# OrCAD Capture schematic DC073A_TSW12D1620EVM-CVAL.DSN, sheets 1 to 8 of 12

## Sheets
1 PAGE08 - MSP430: size B; title: SCH, TSW12D1620EVM-CVAL; rev: A; note: DC073
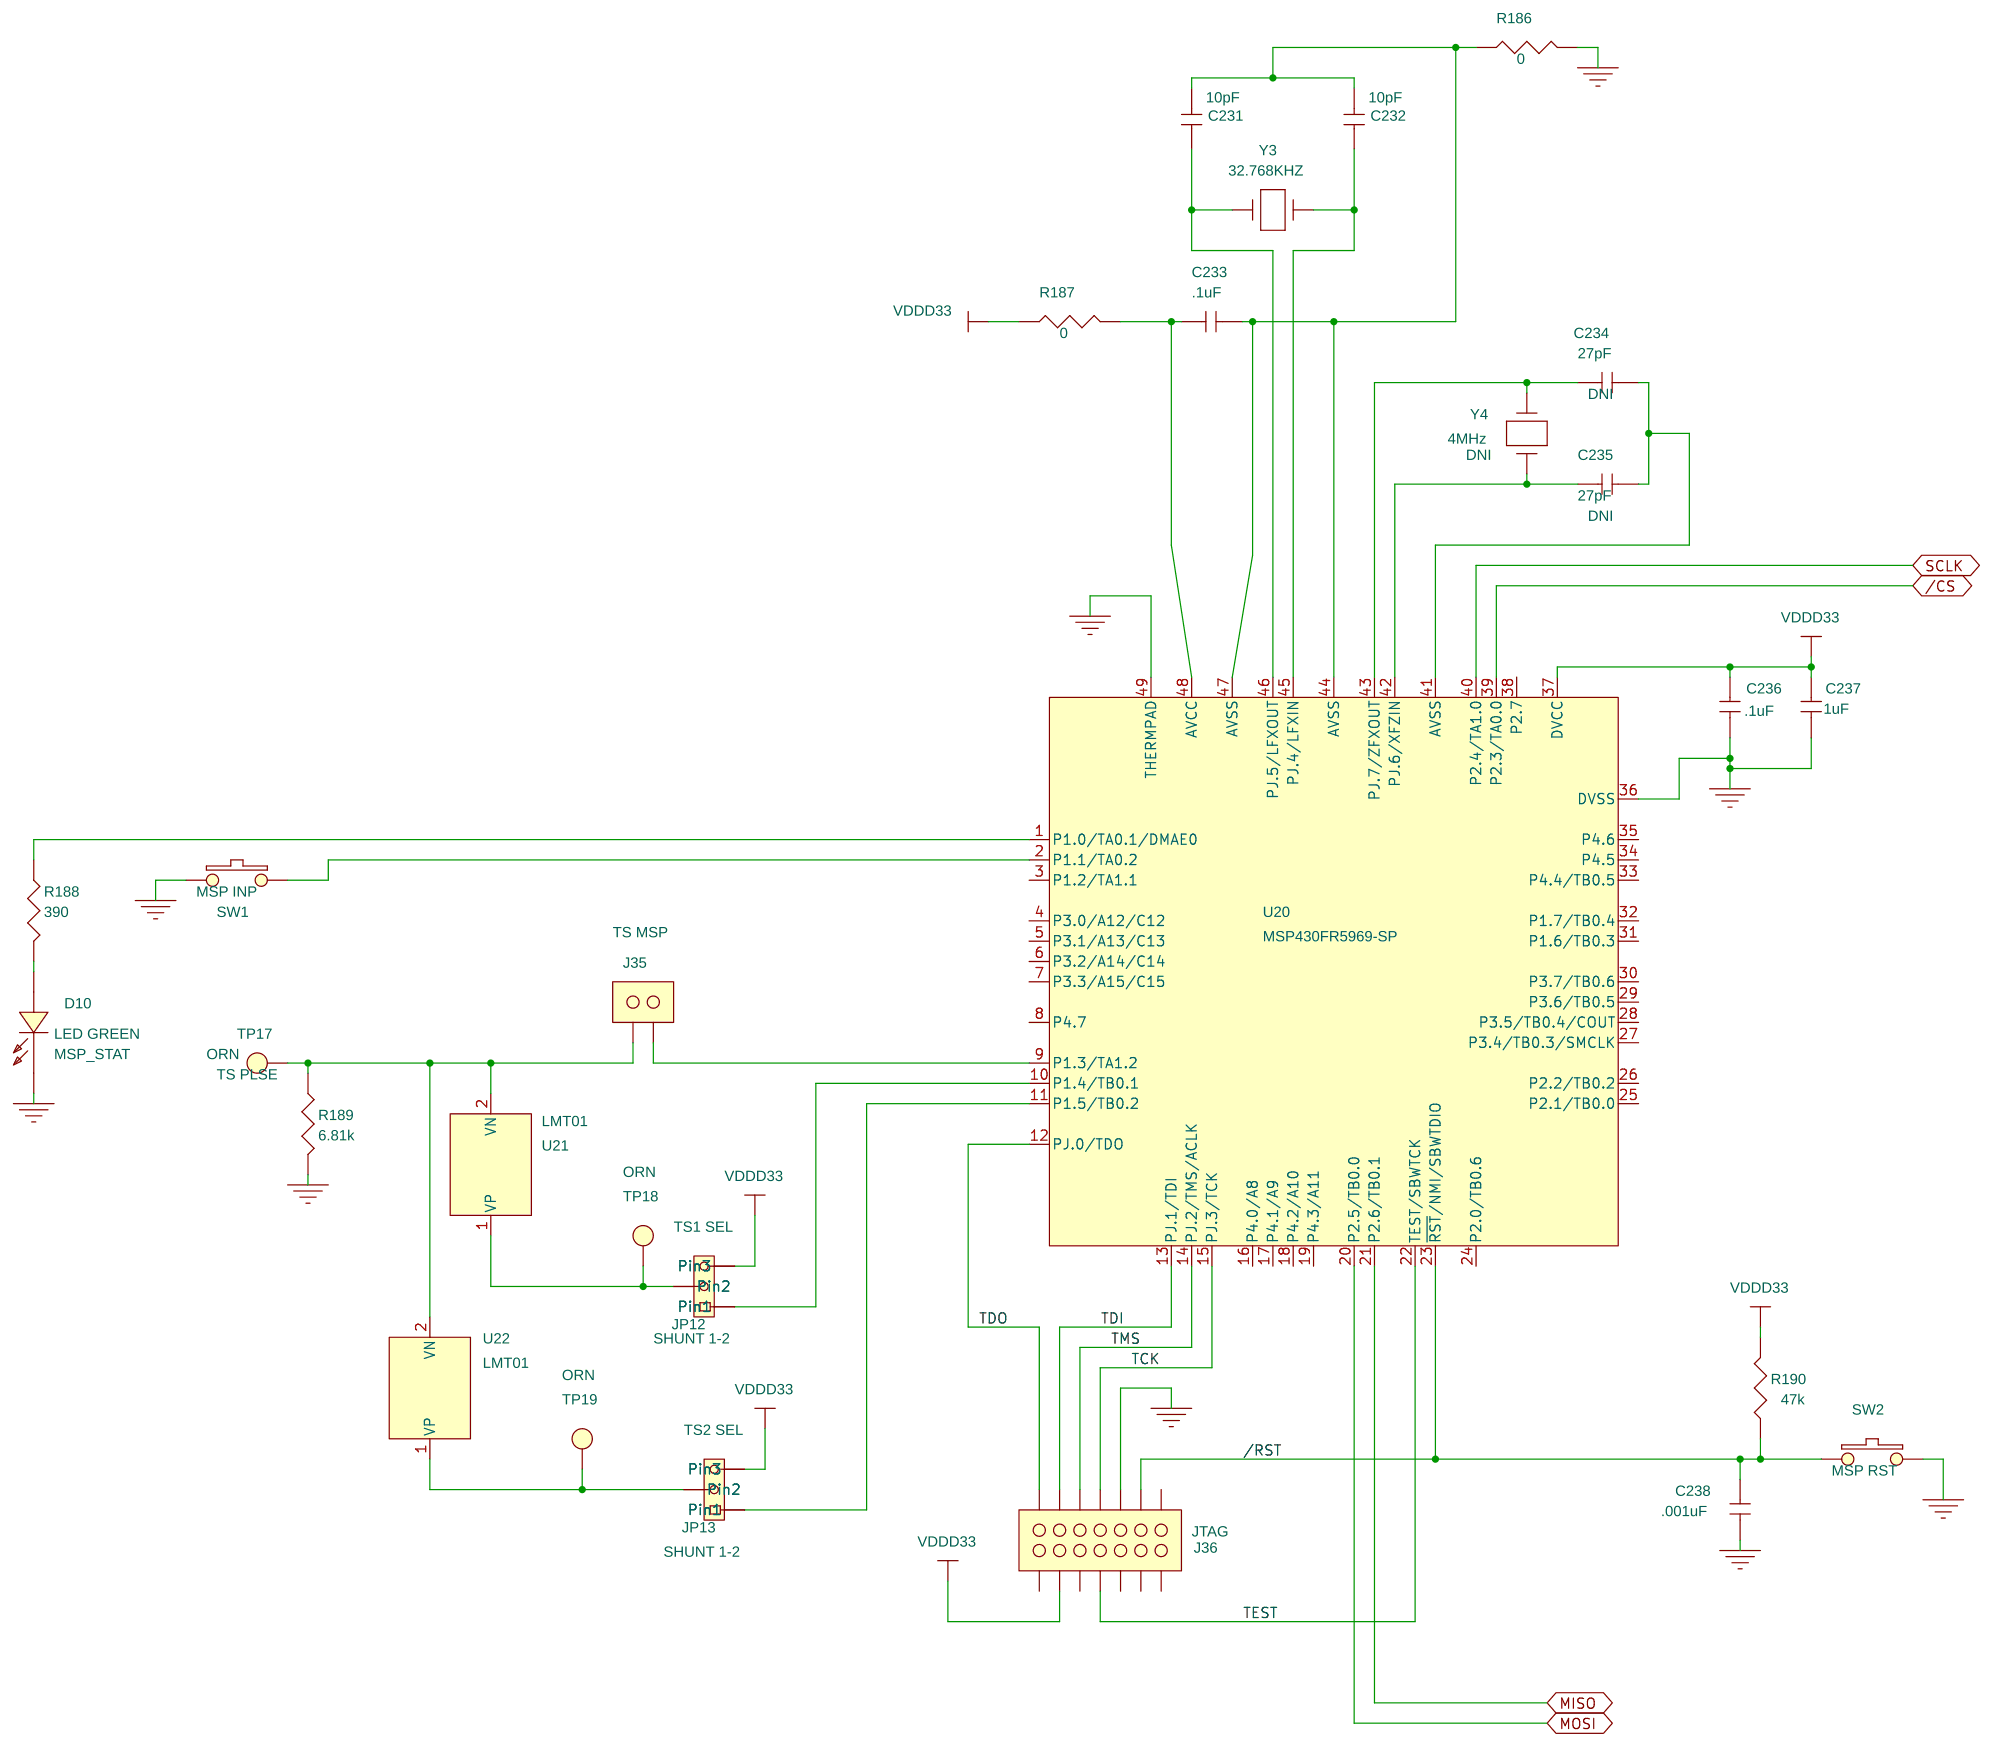
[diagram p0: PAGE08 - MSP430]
2 PAGE01 - BLOCK DIAGRAM
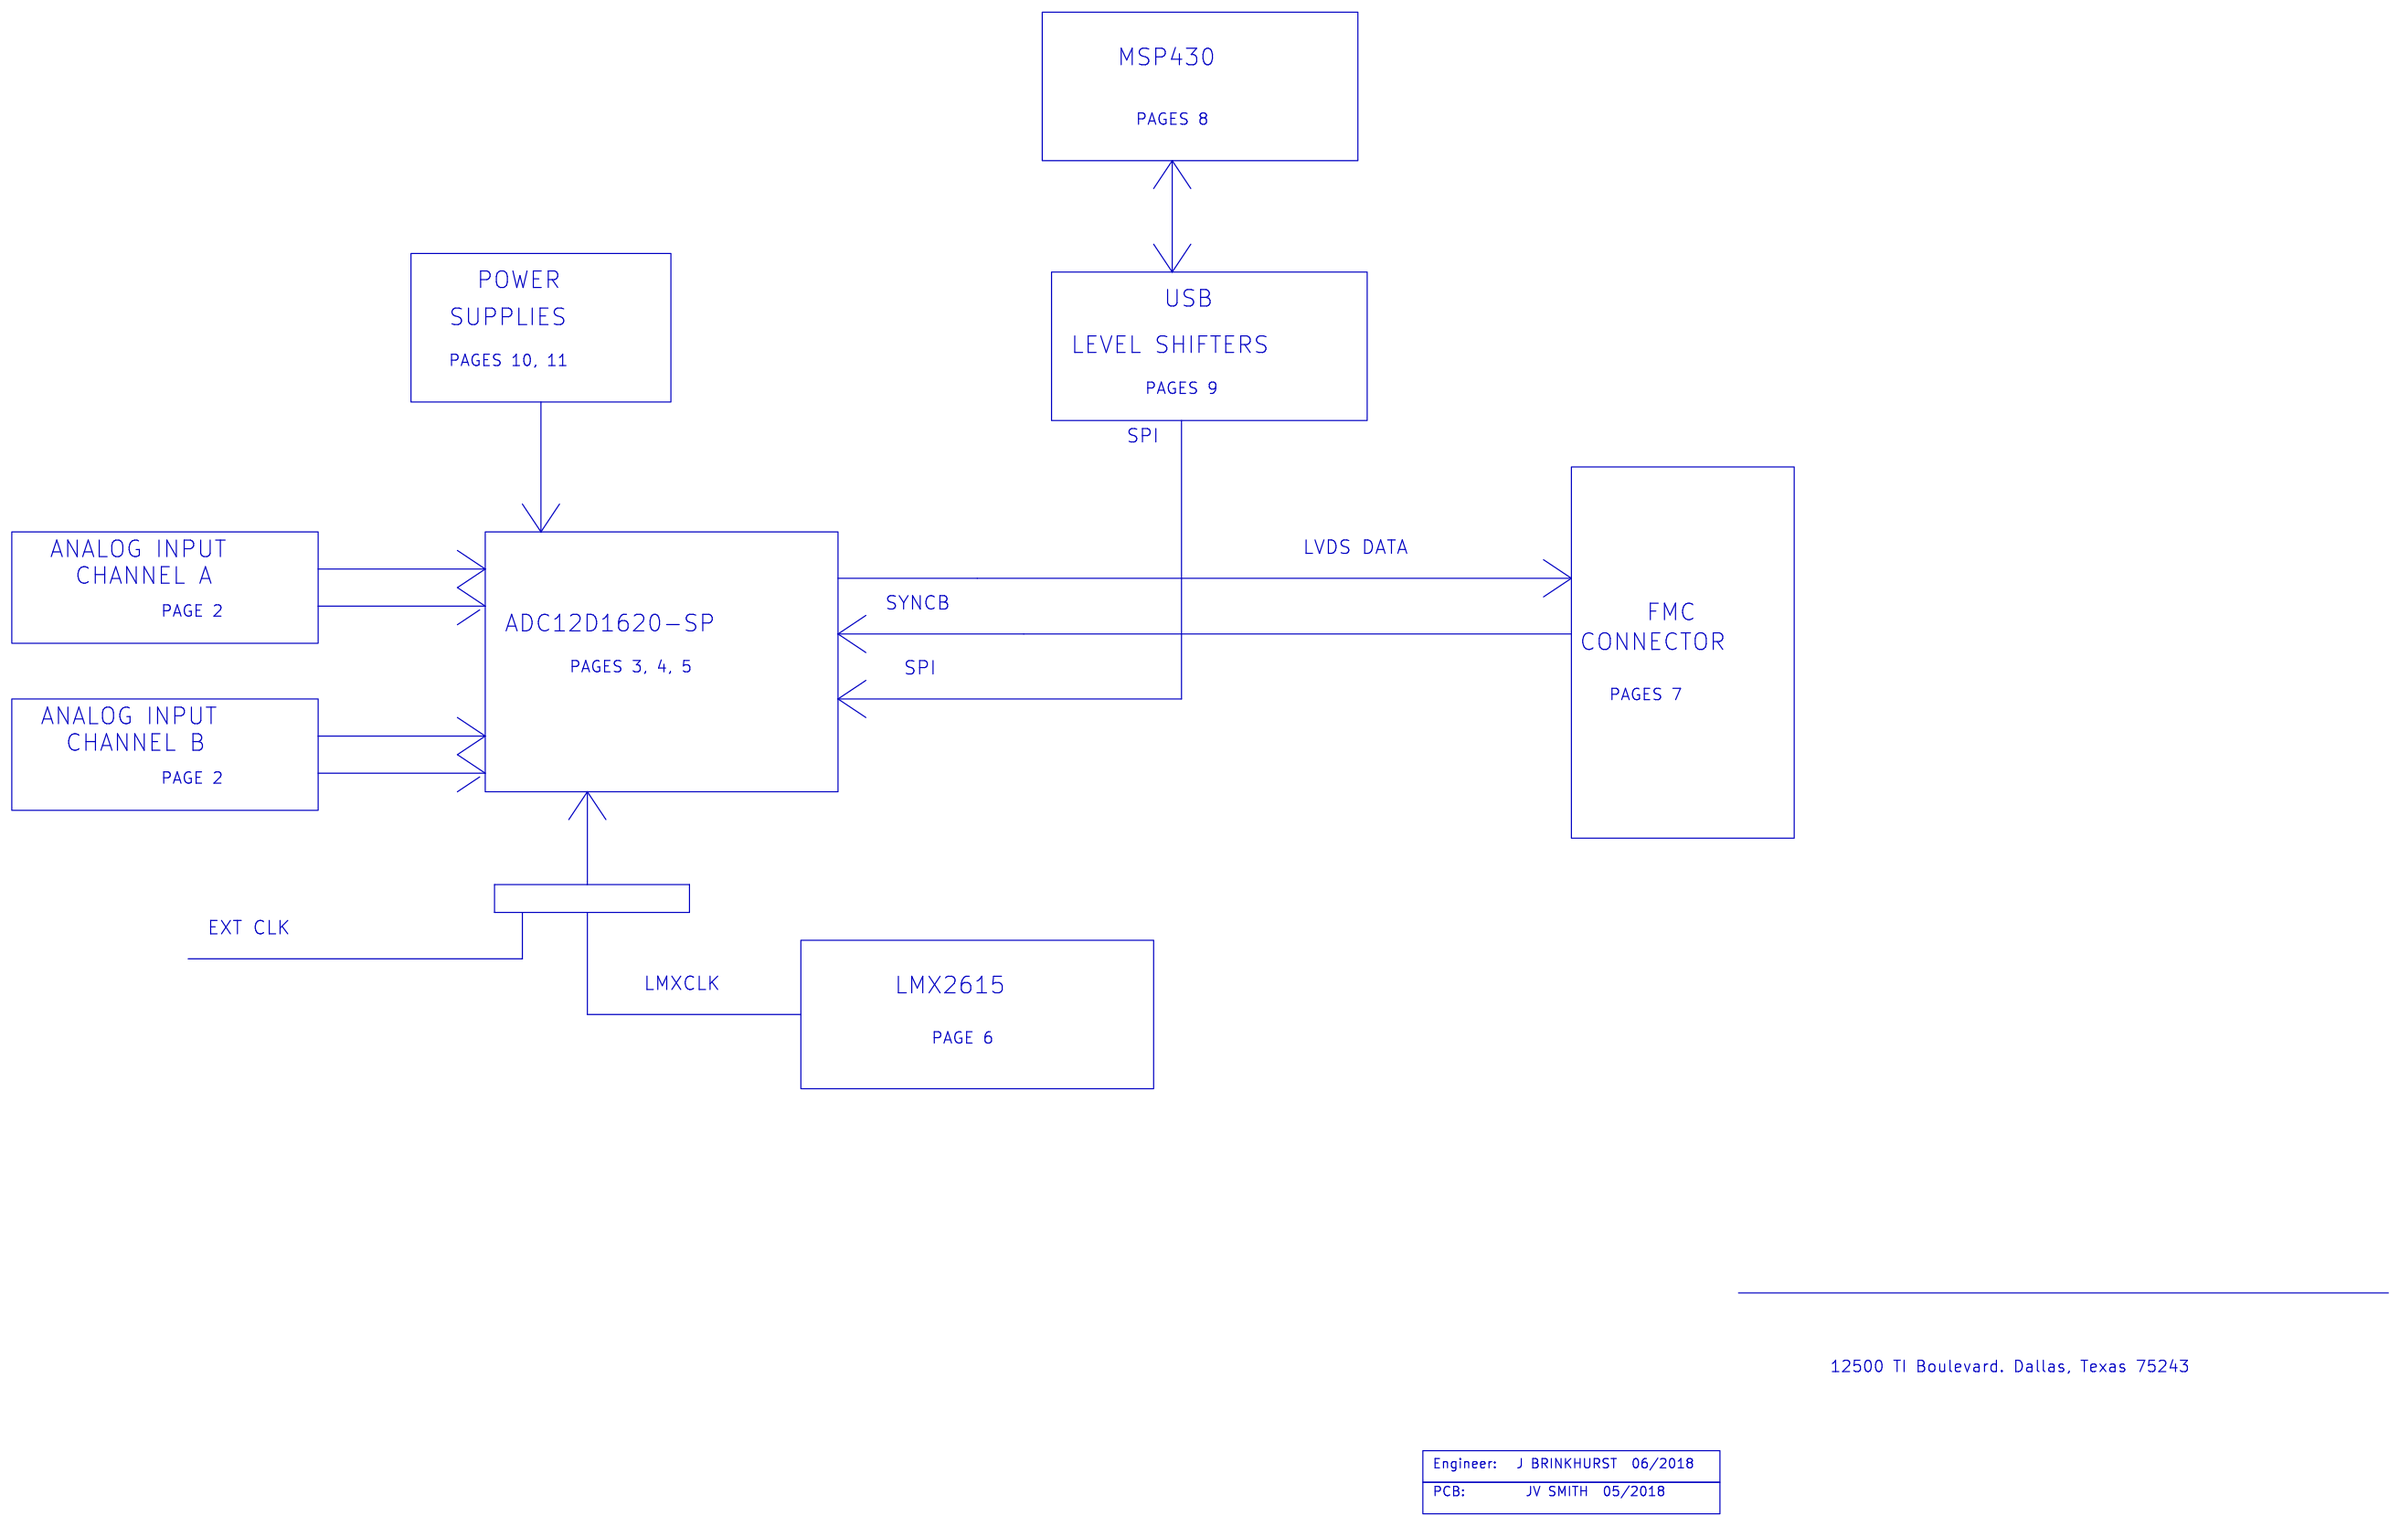
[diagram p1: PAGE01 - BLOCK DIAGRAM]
3 PAGE02 - ADC ANALOG INPUT: size B
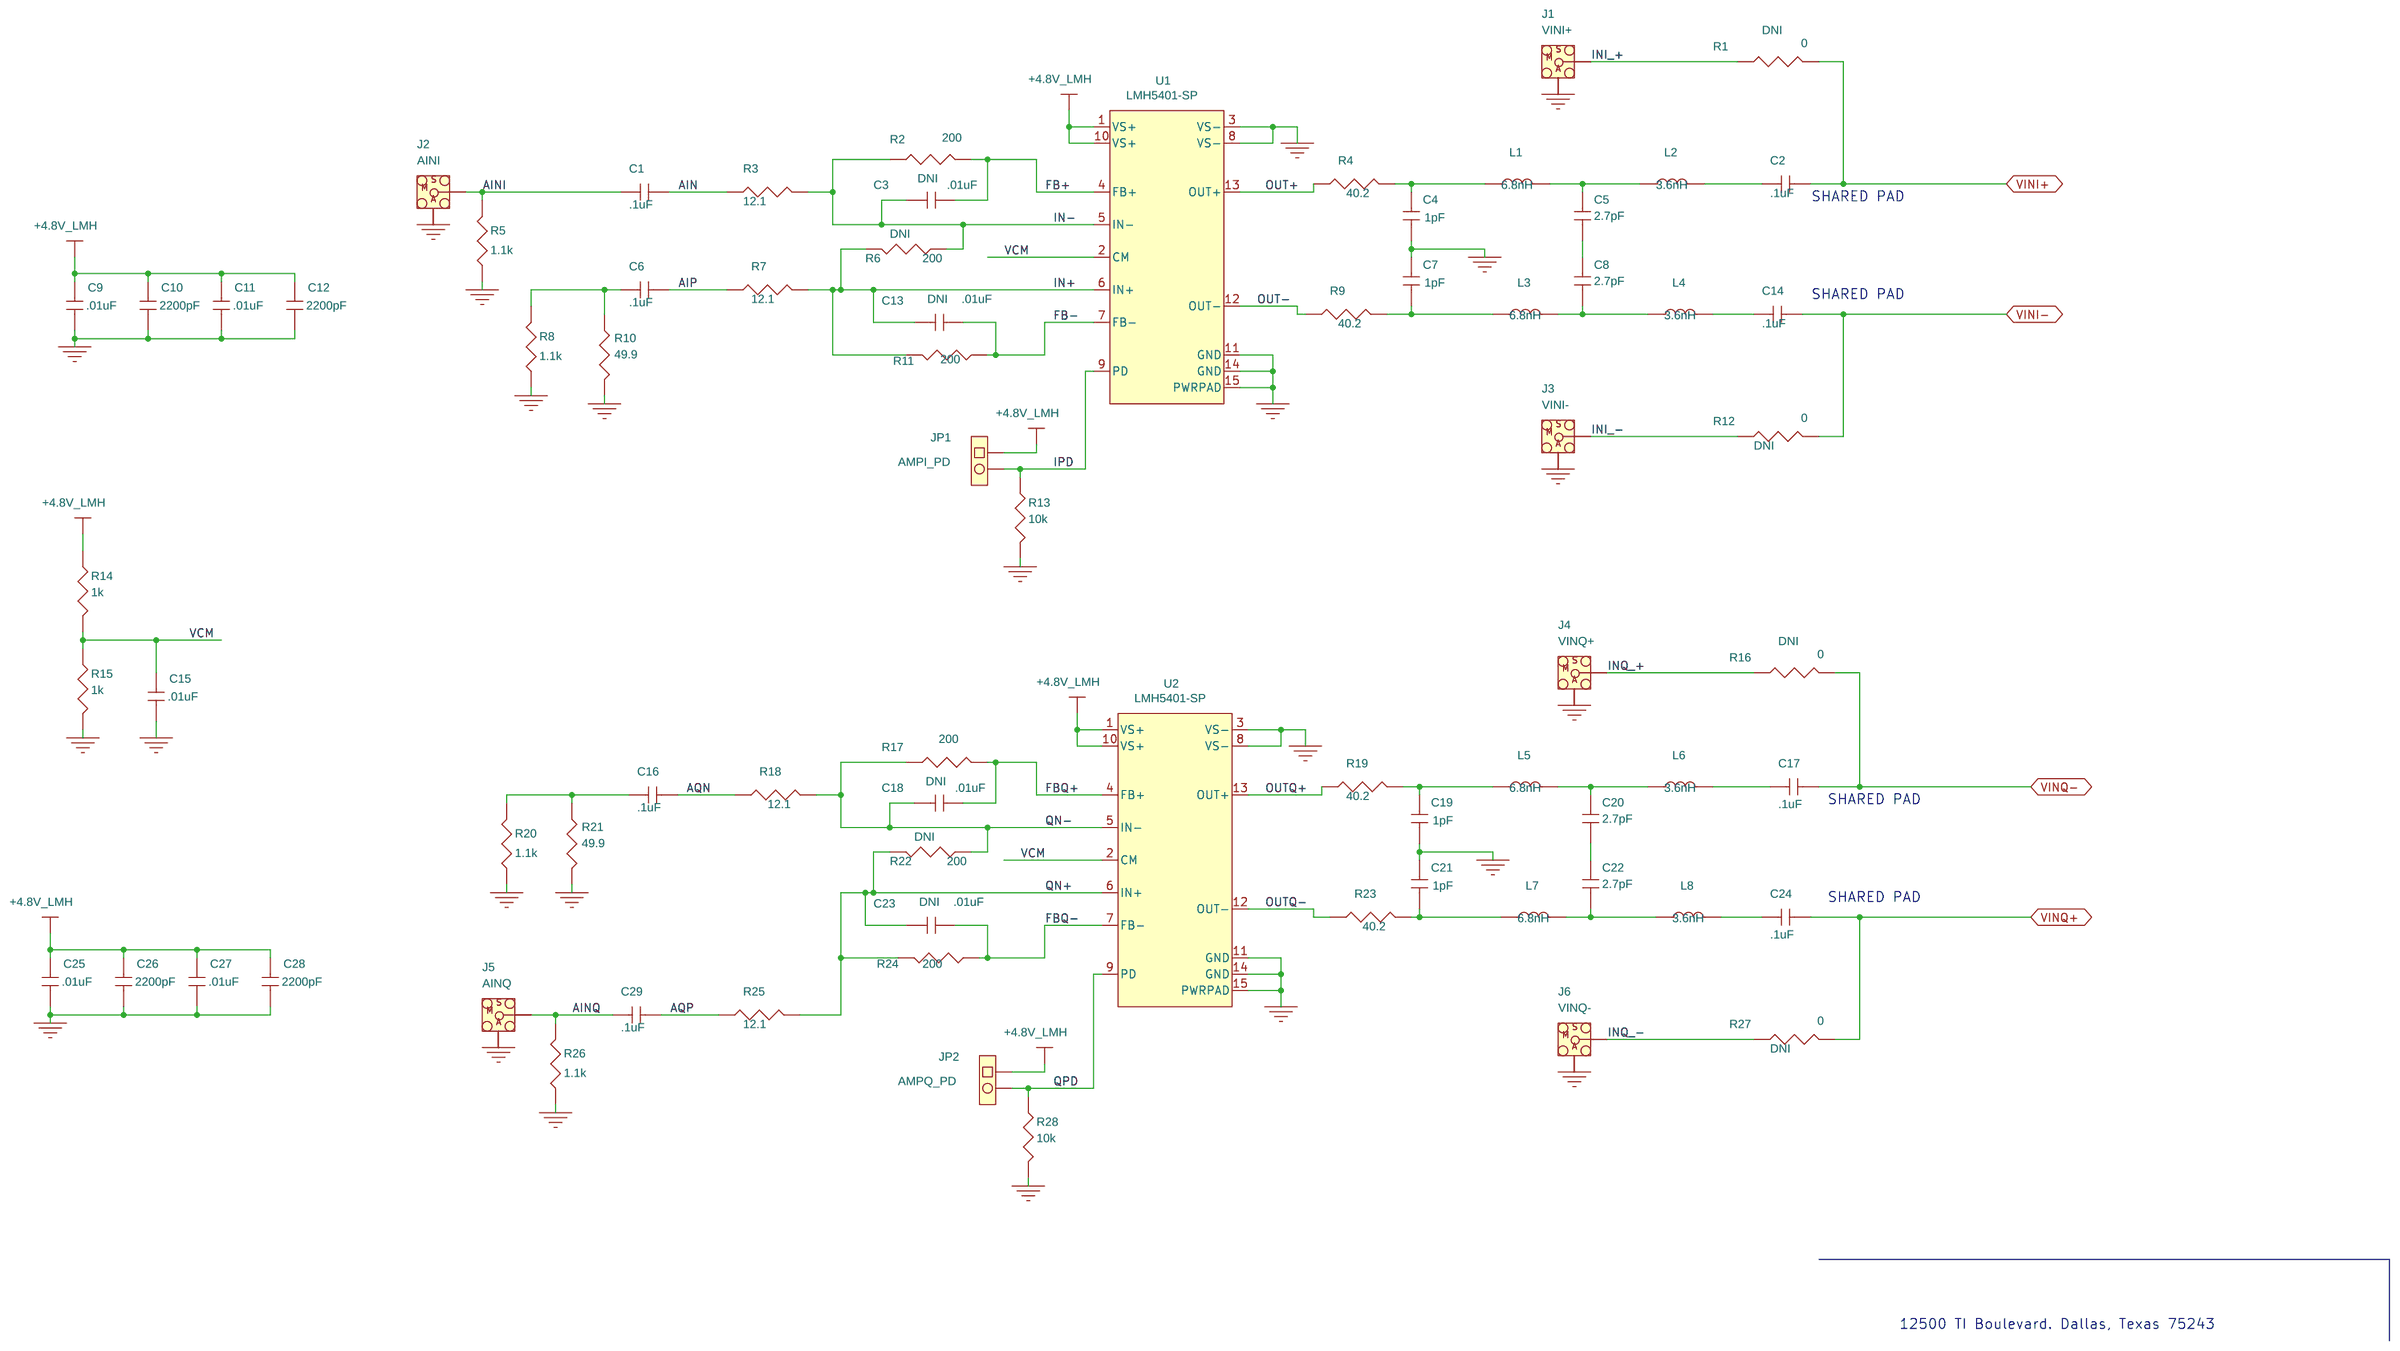
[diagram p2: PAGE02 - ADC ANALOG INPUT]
4 PAGE03 - ADC SPI: size B
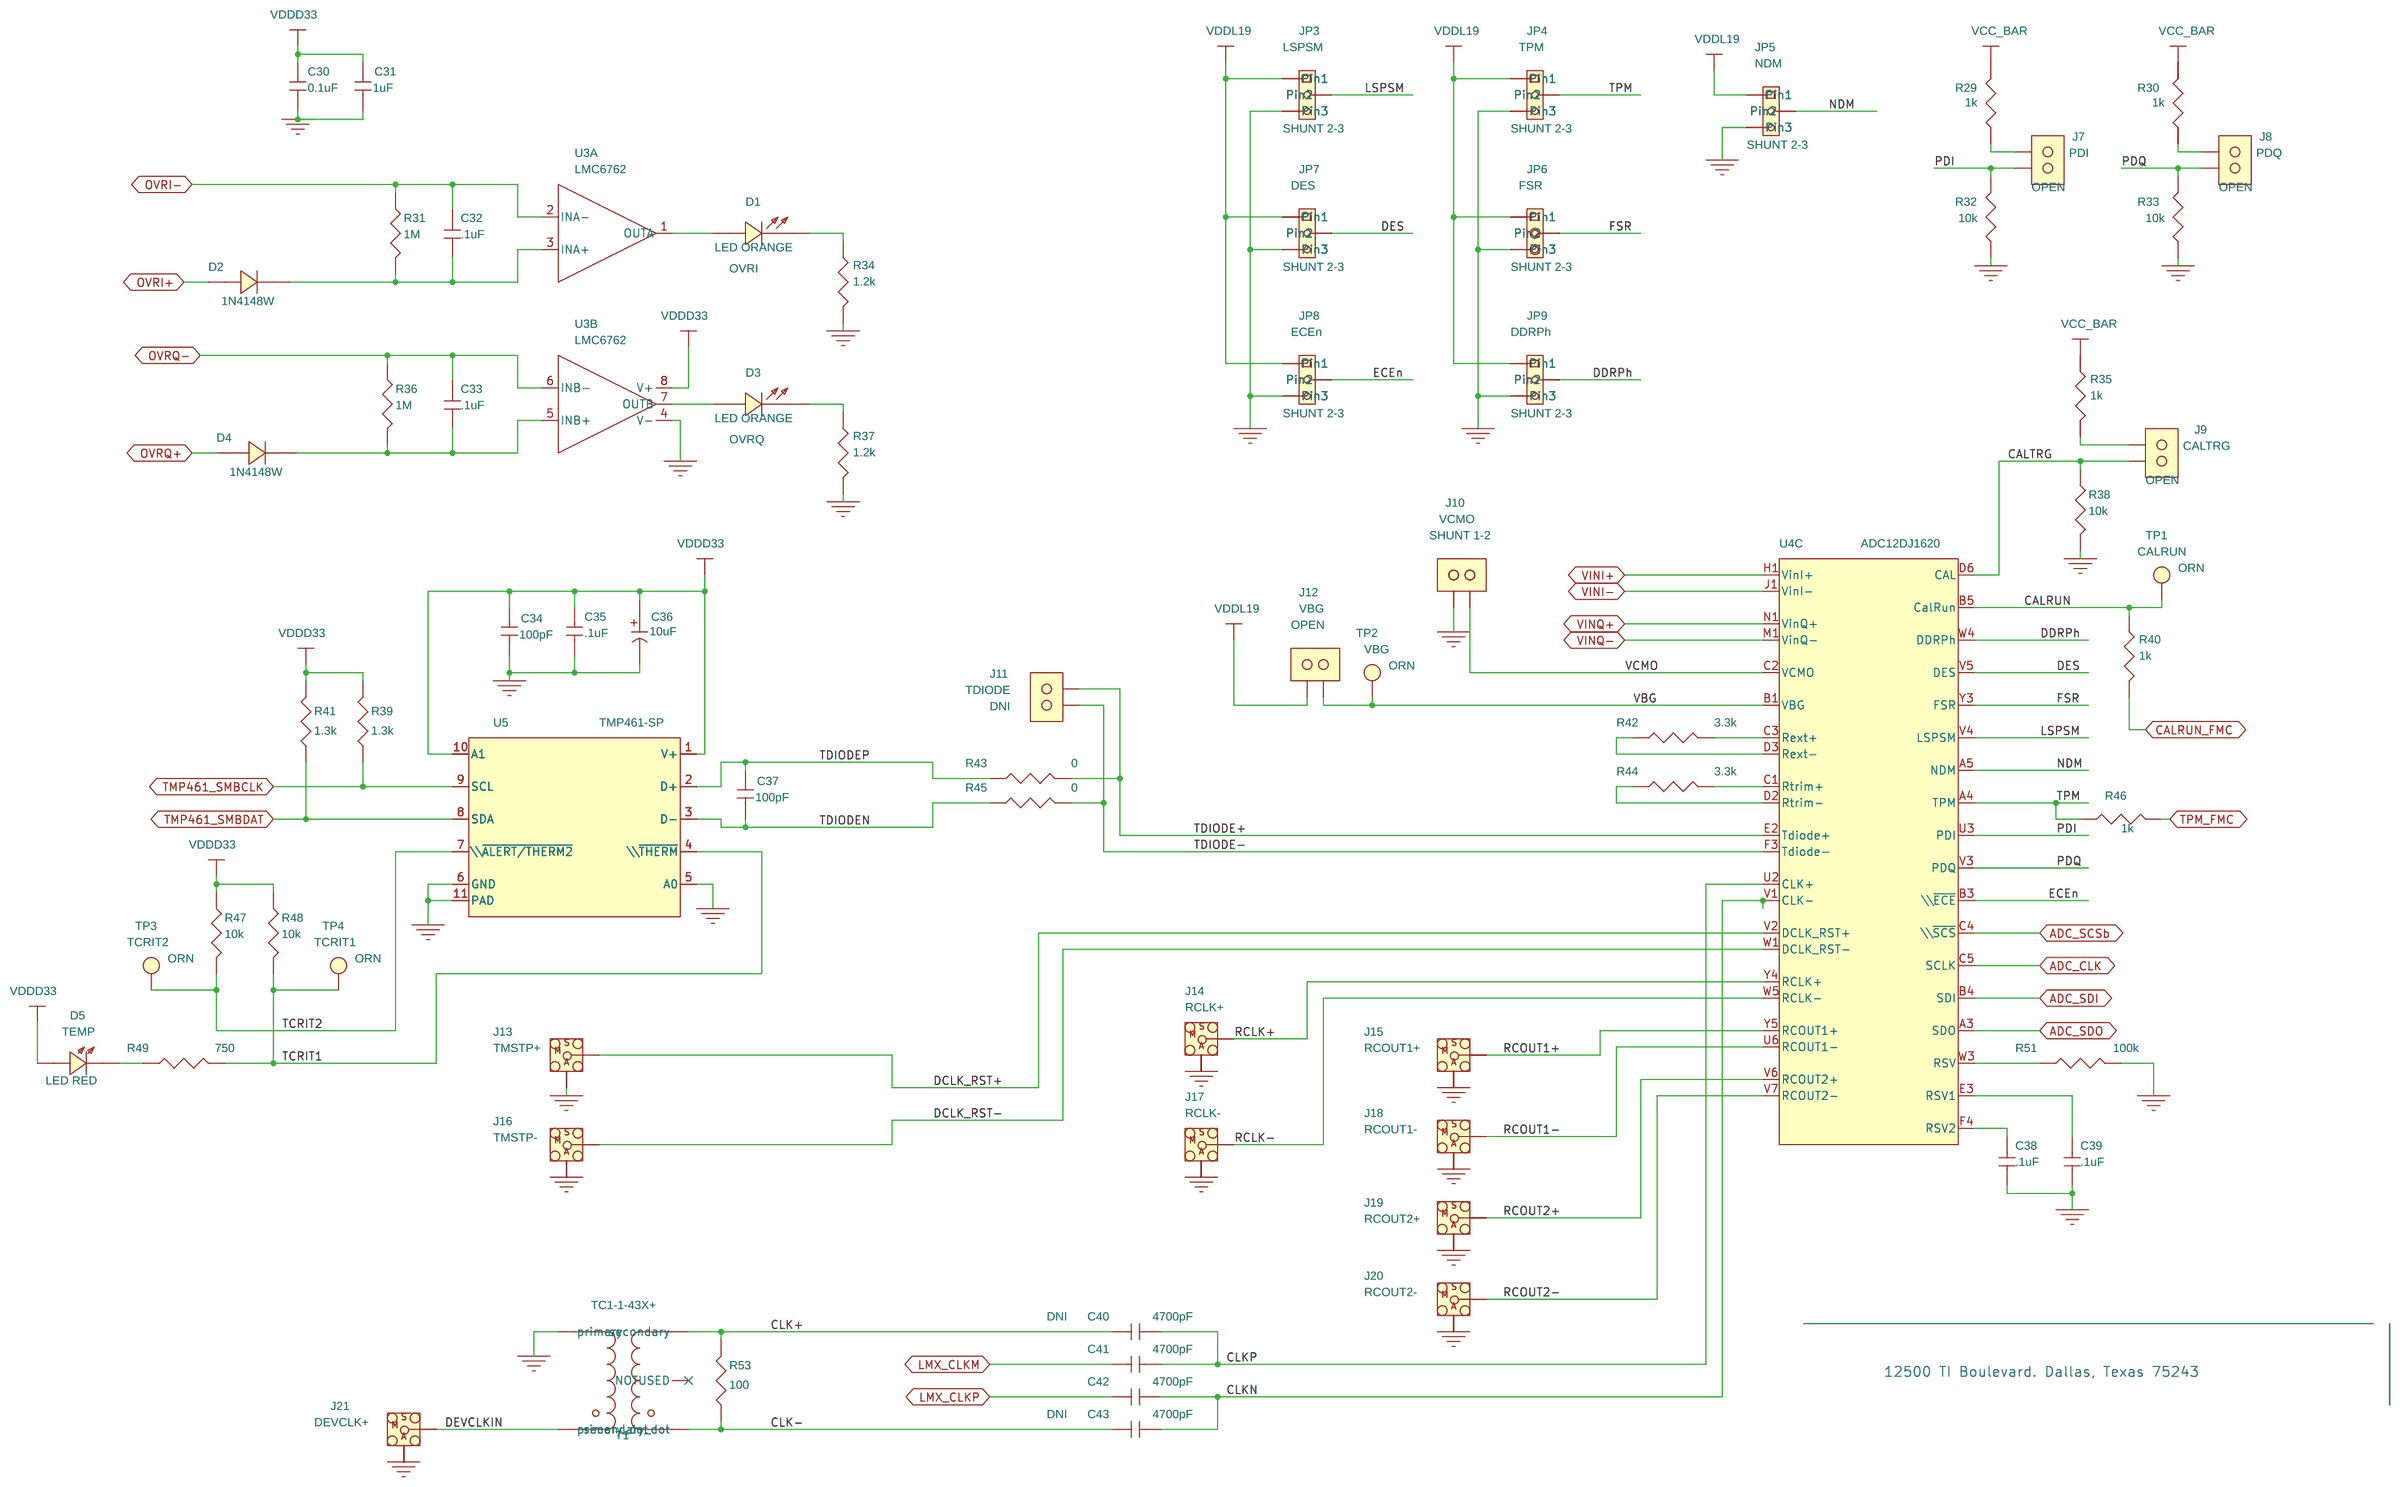
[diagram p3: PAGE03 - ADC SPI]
5 PAGE04 - ADC FMC CONNECTIONS: size B
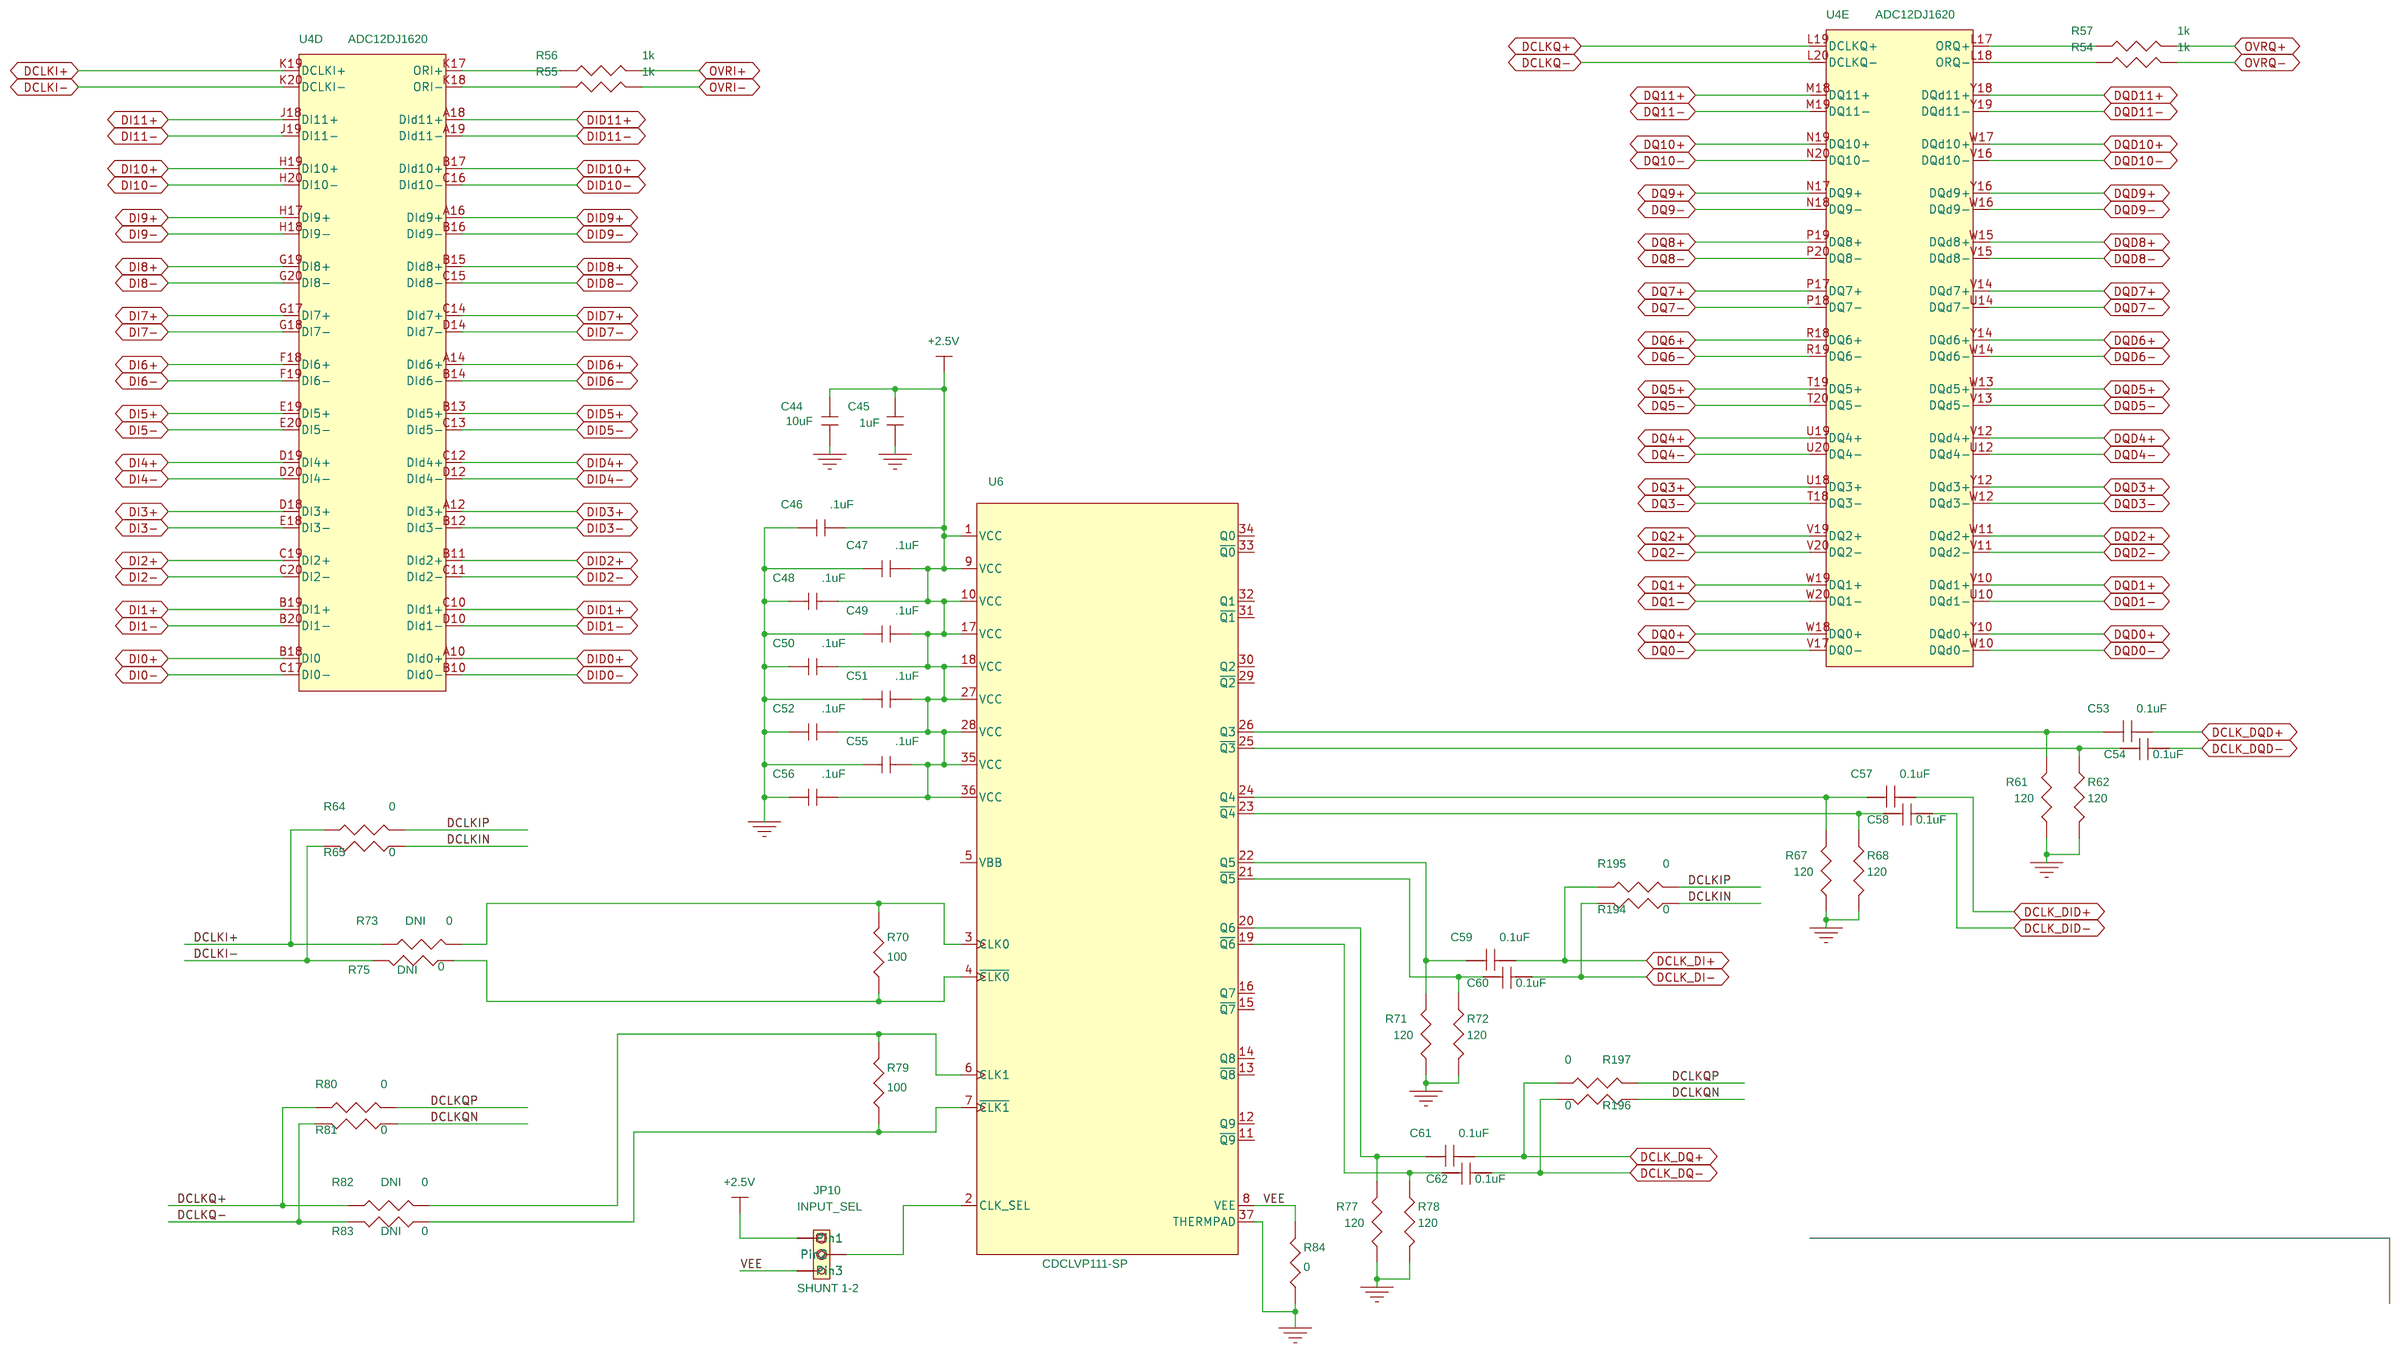
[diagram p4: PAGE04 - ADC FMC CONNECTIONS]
6 PAGE05 - ADC PWR: size B
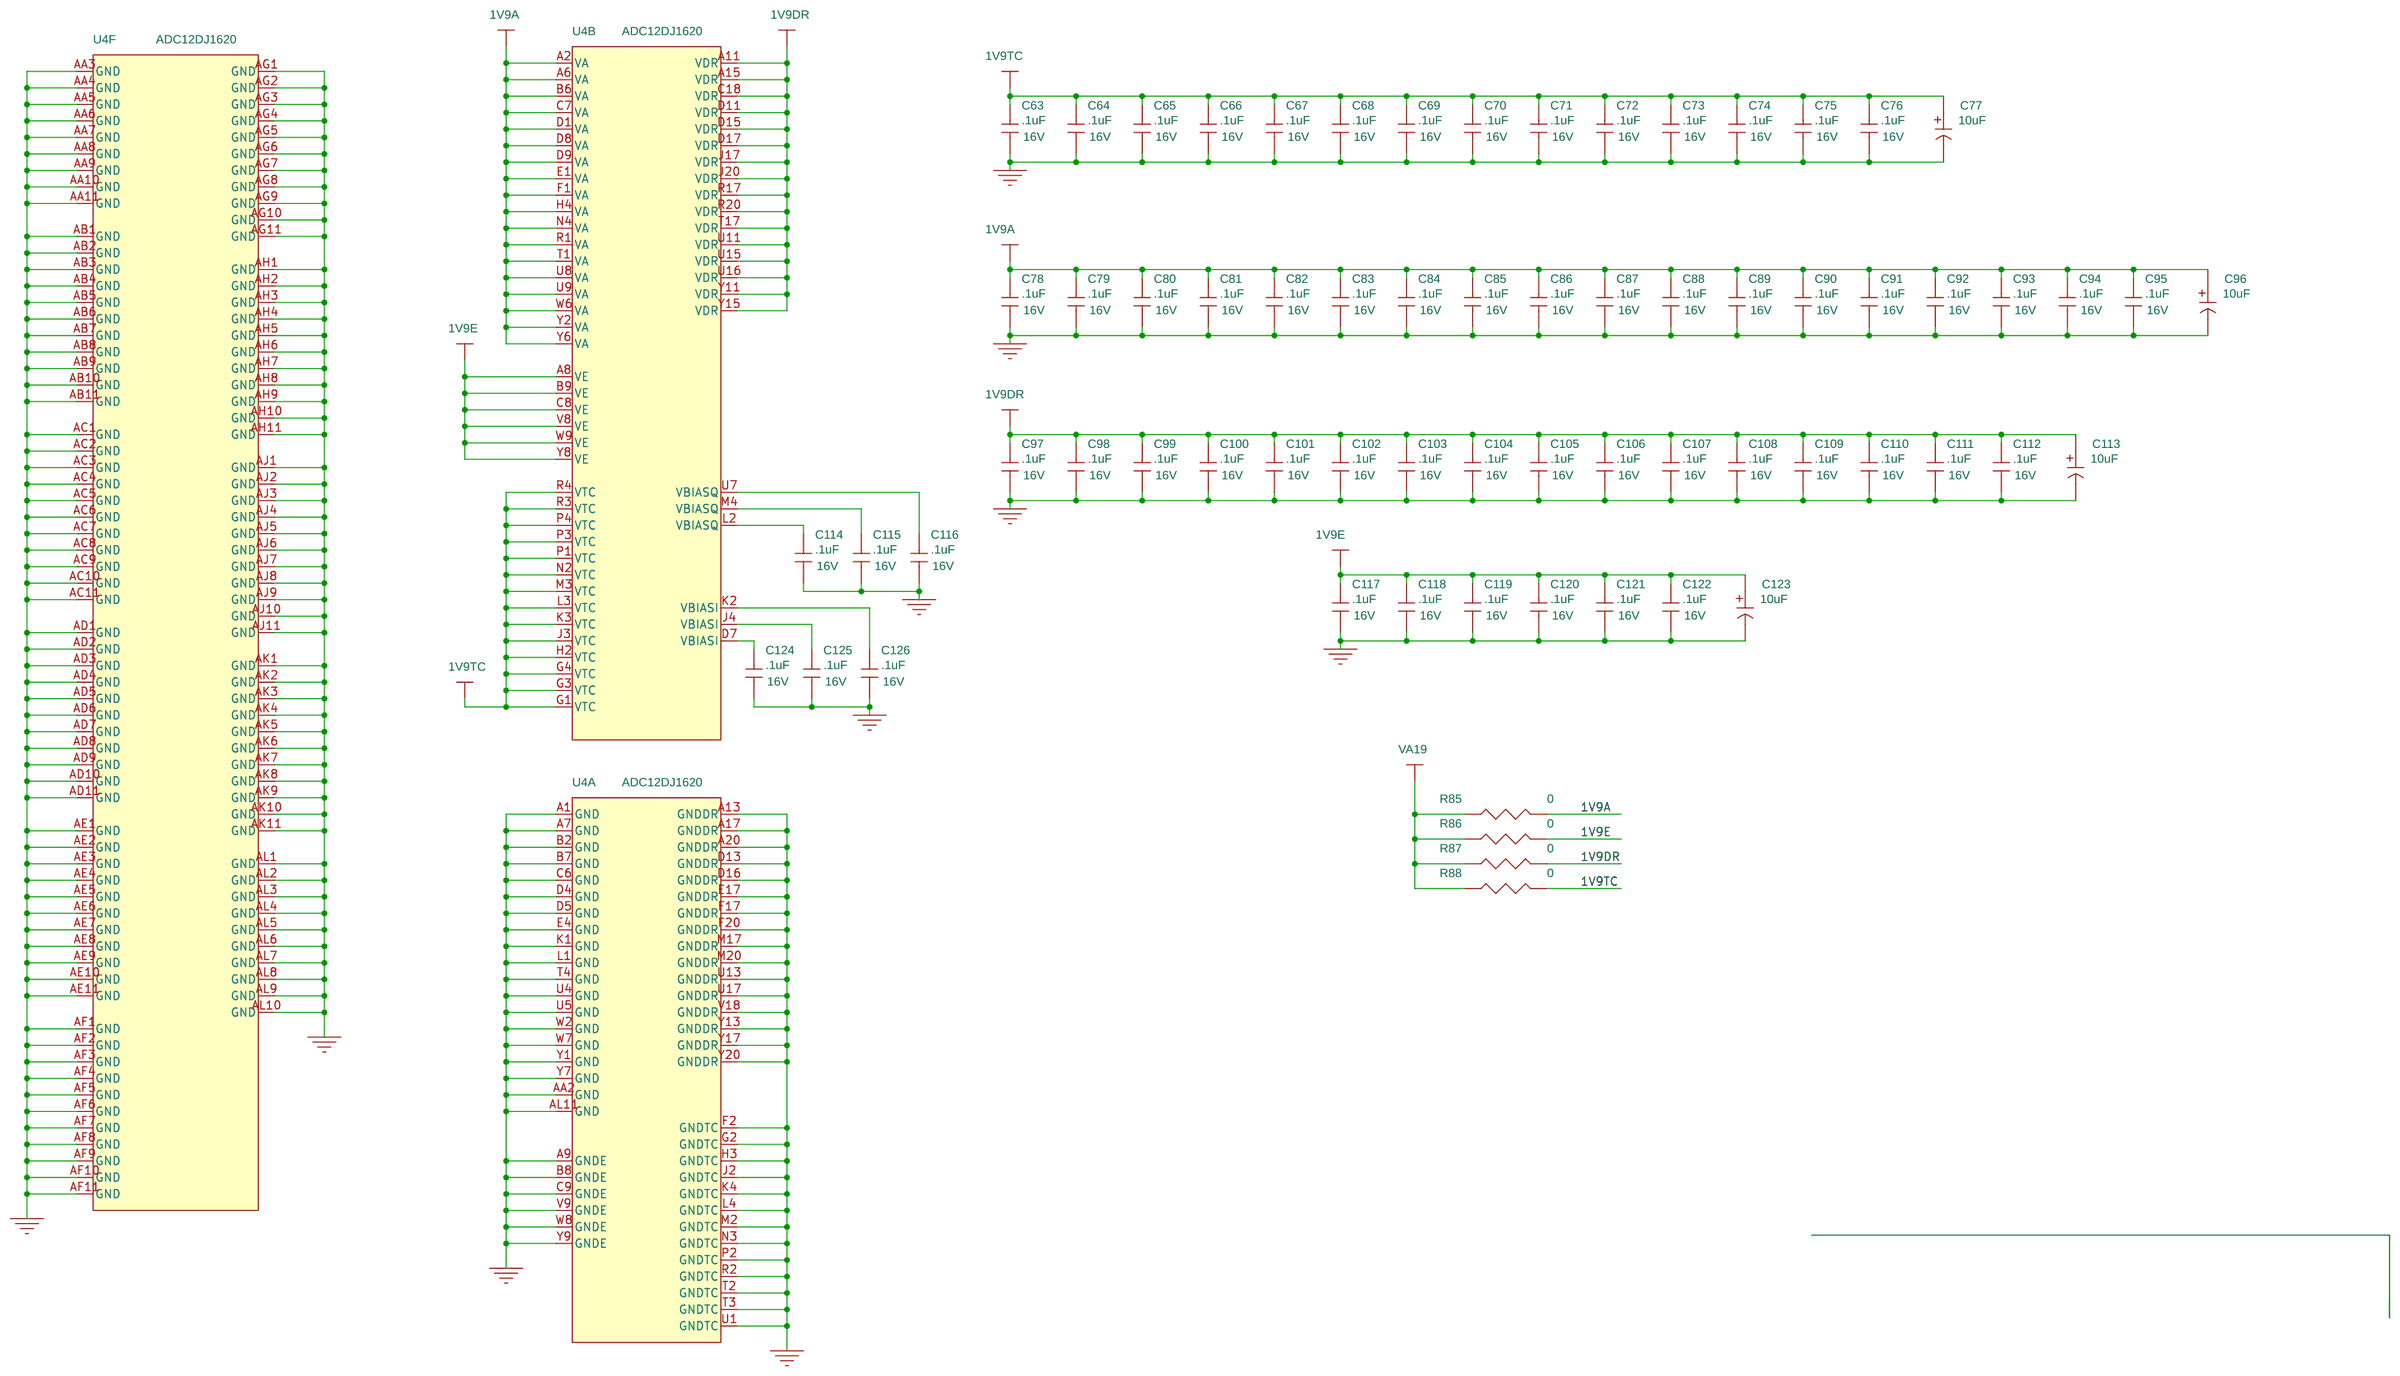
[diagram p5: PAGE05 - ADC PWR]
7 PAGE06 - LMX: size B
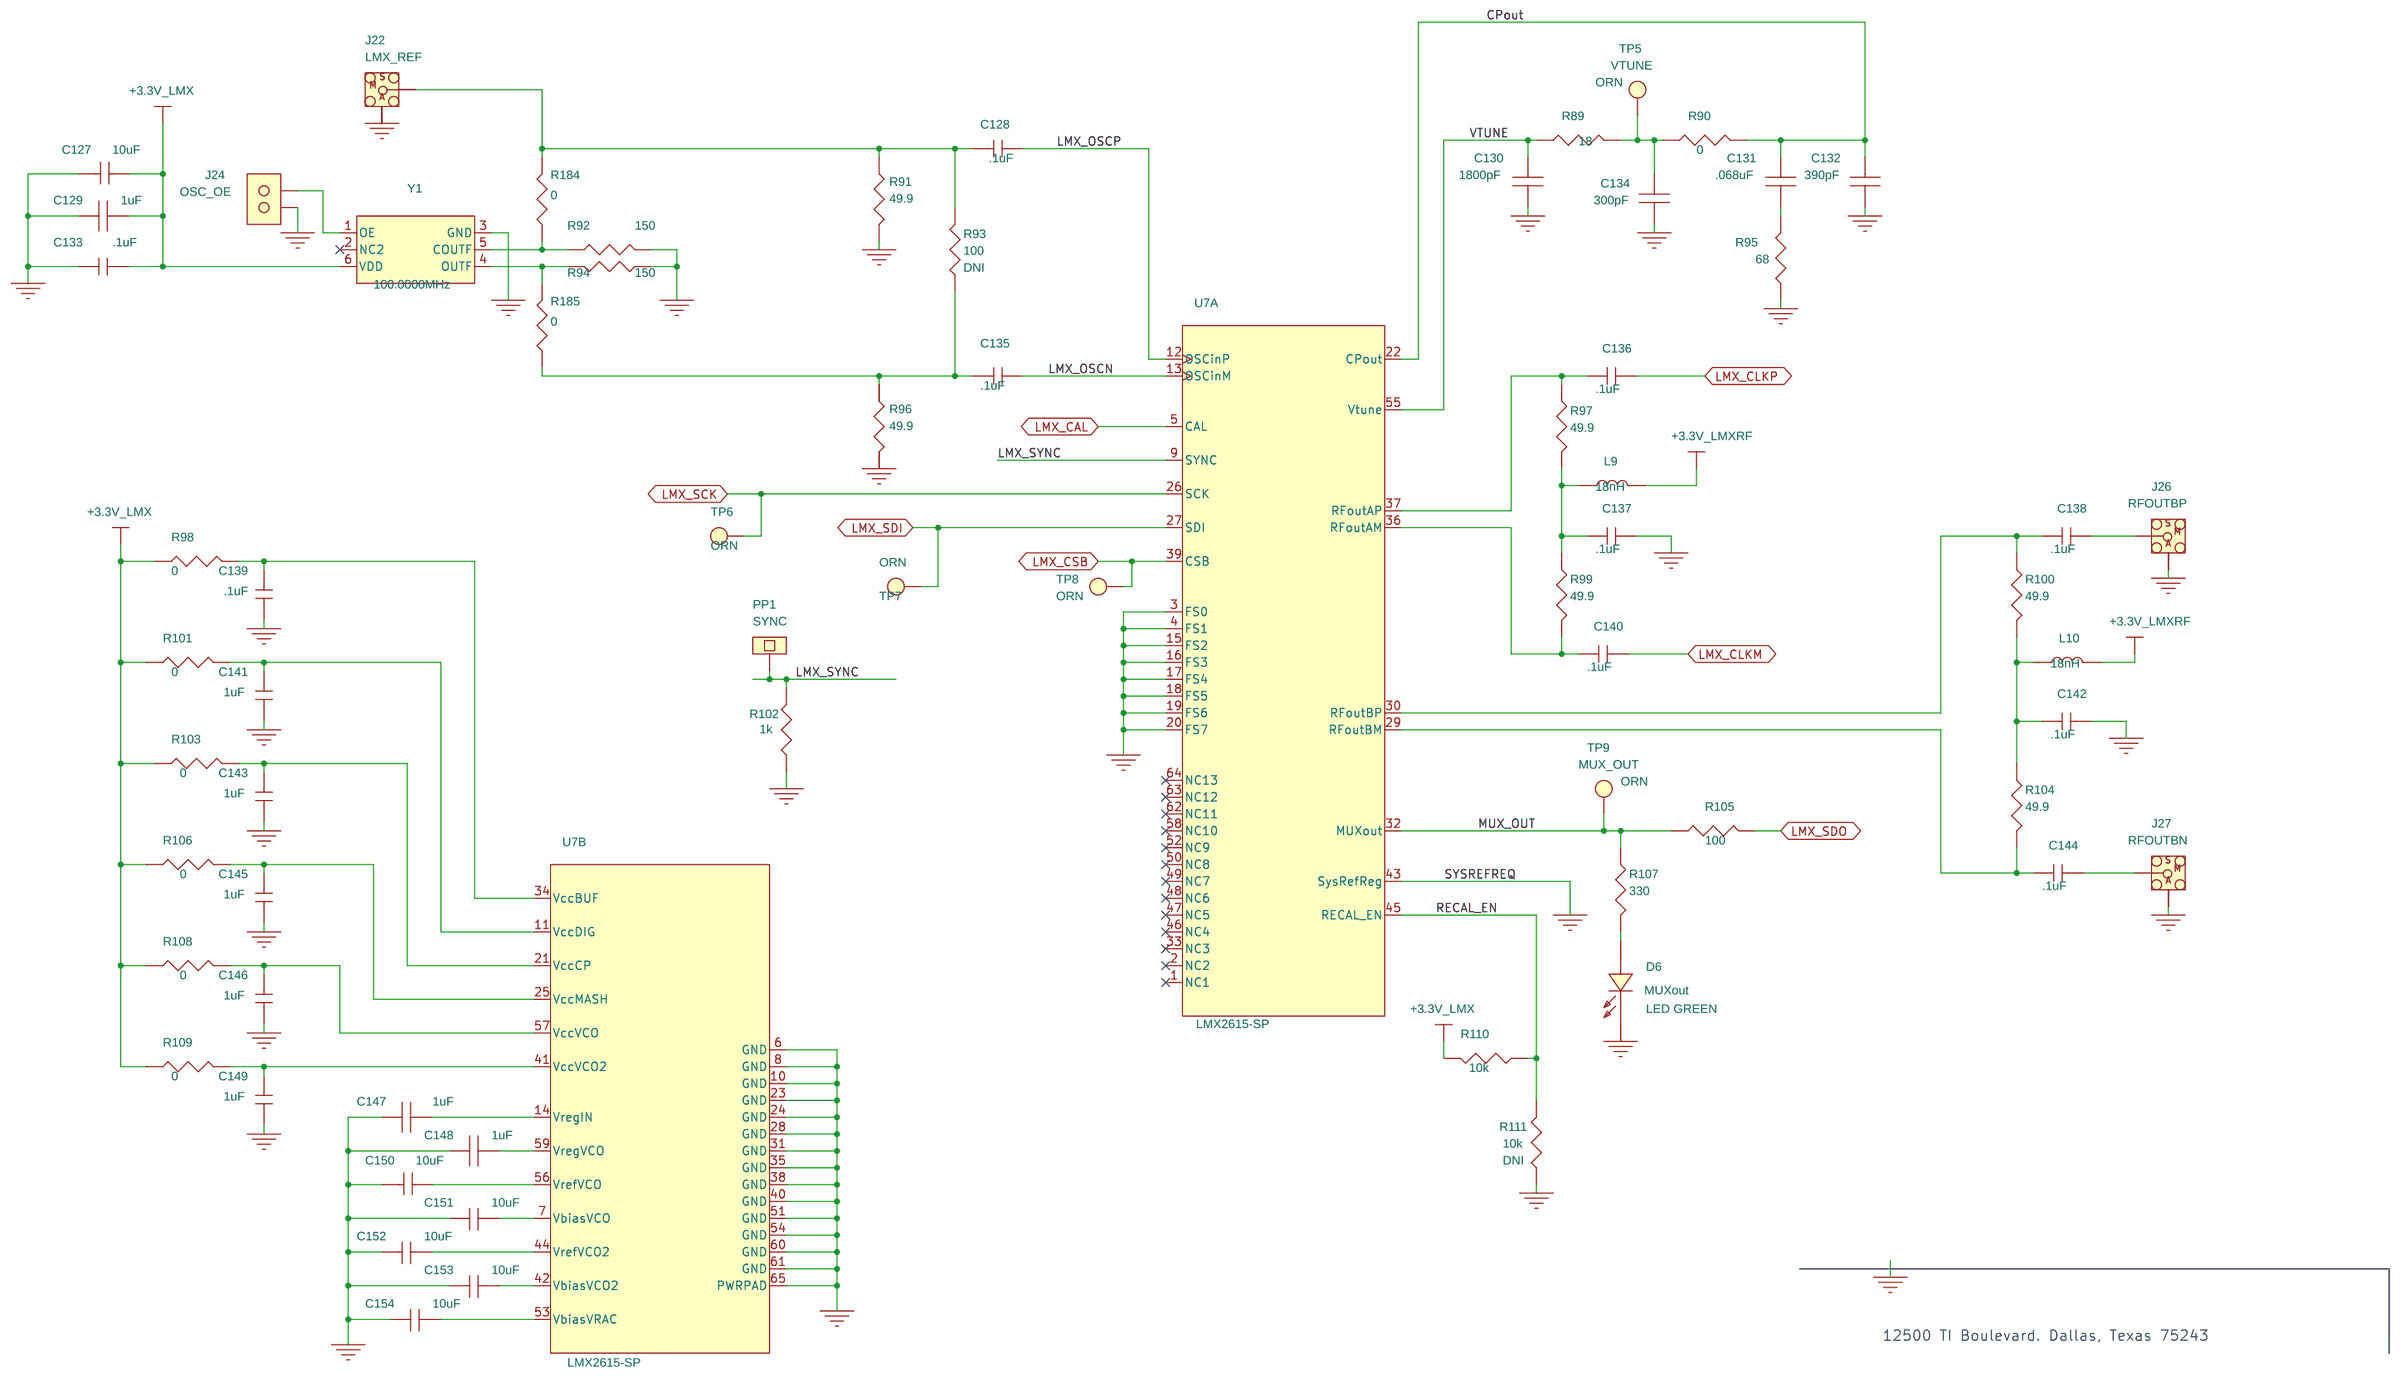
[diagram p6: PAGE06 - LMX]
8 PAGE07 - OUTPUT FMC CONN: size B
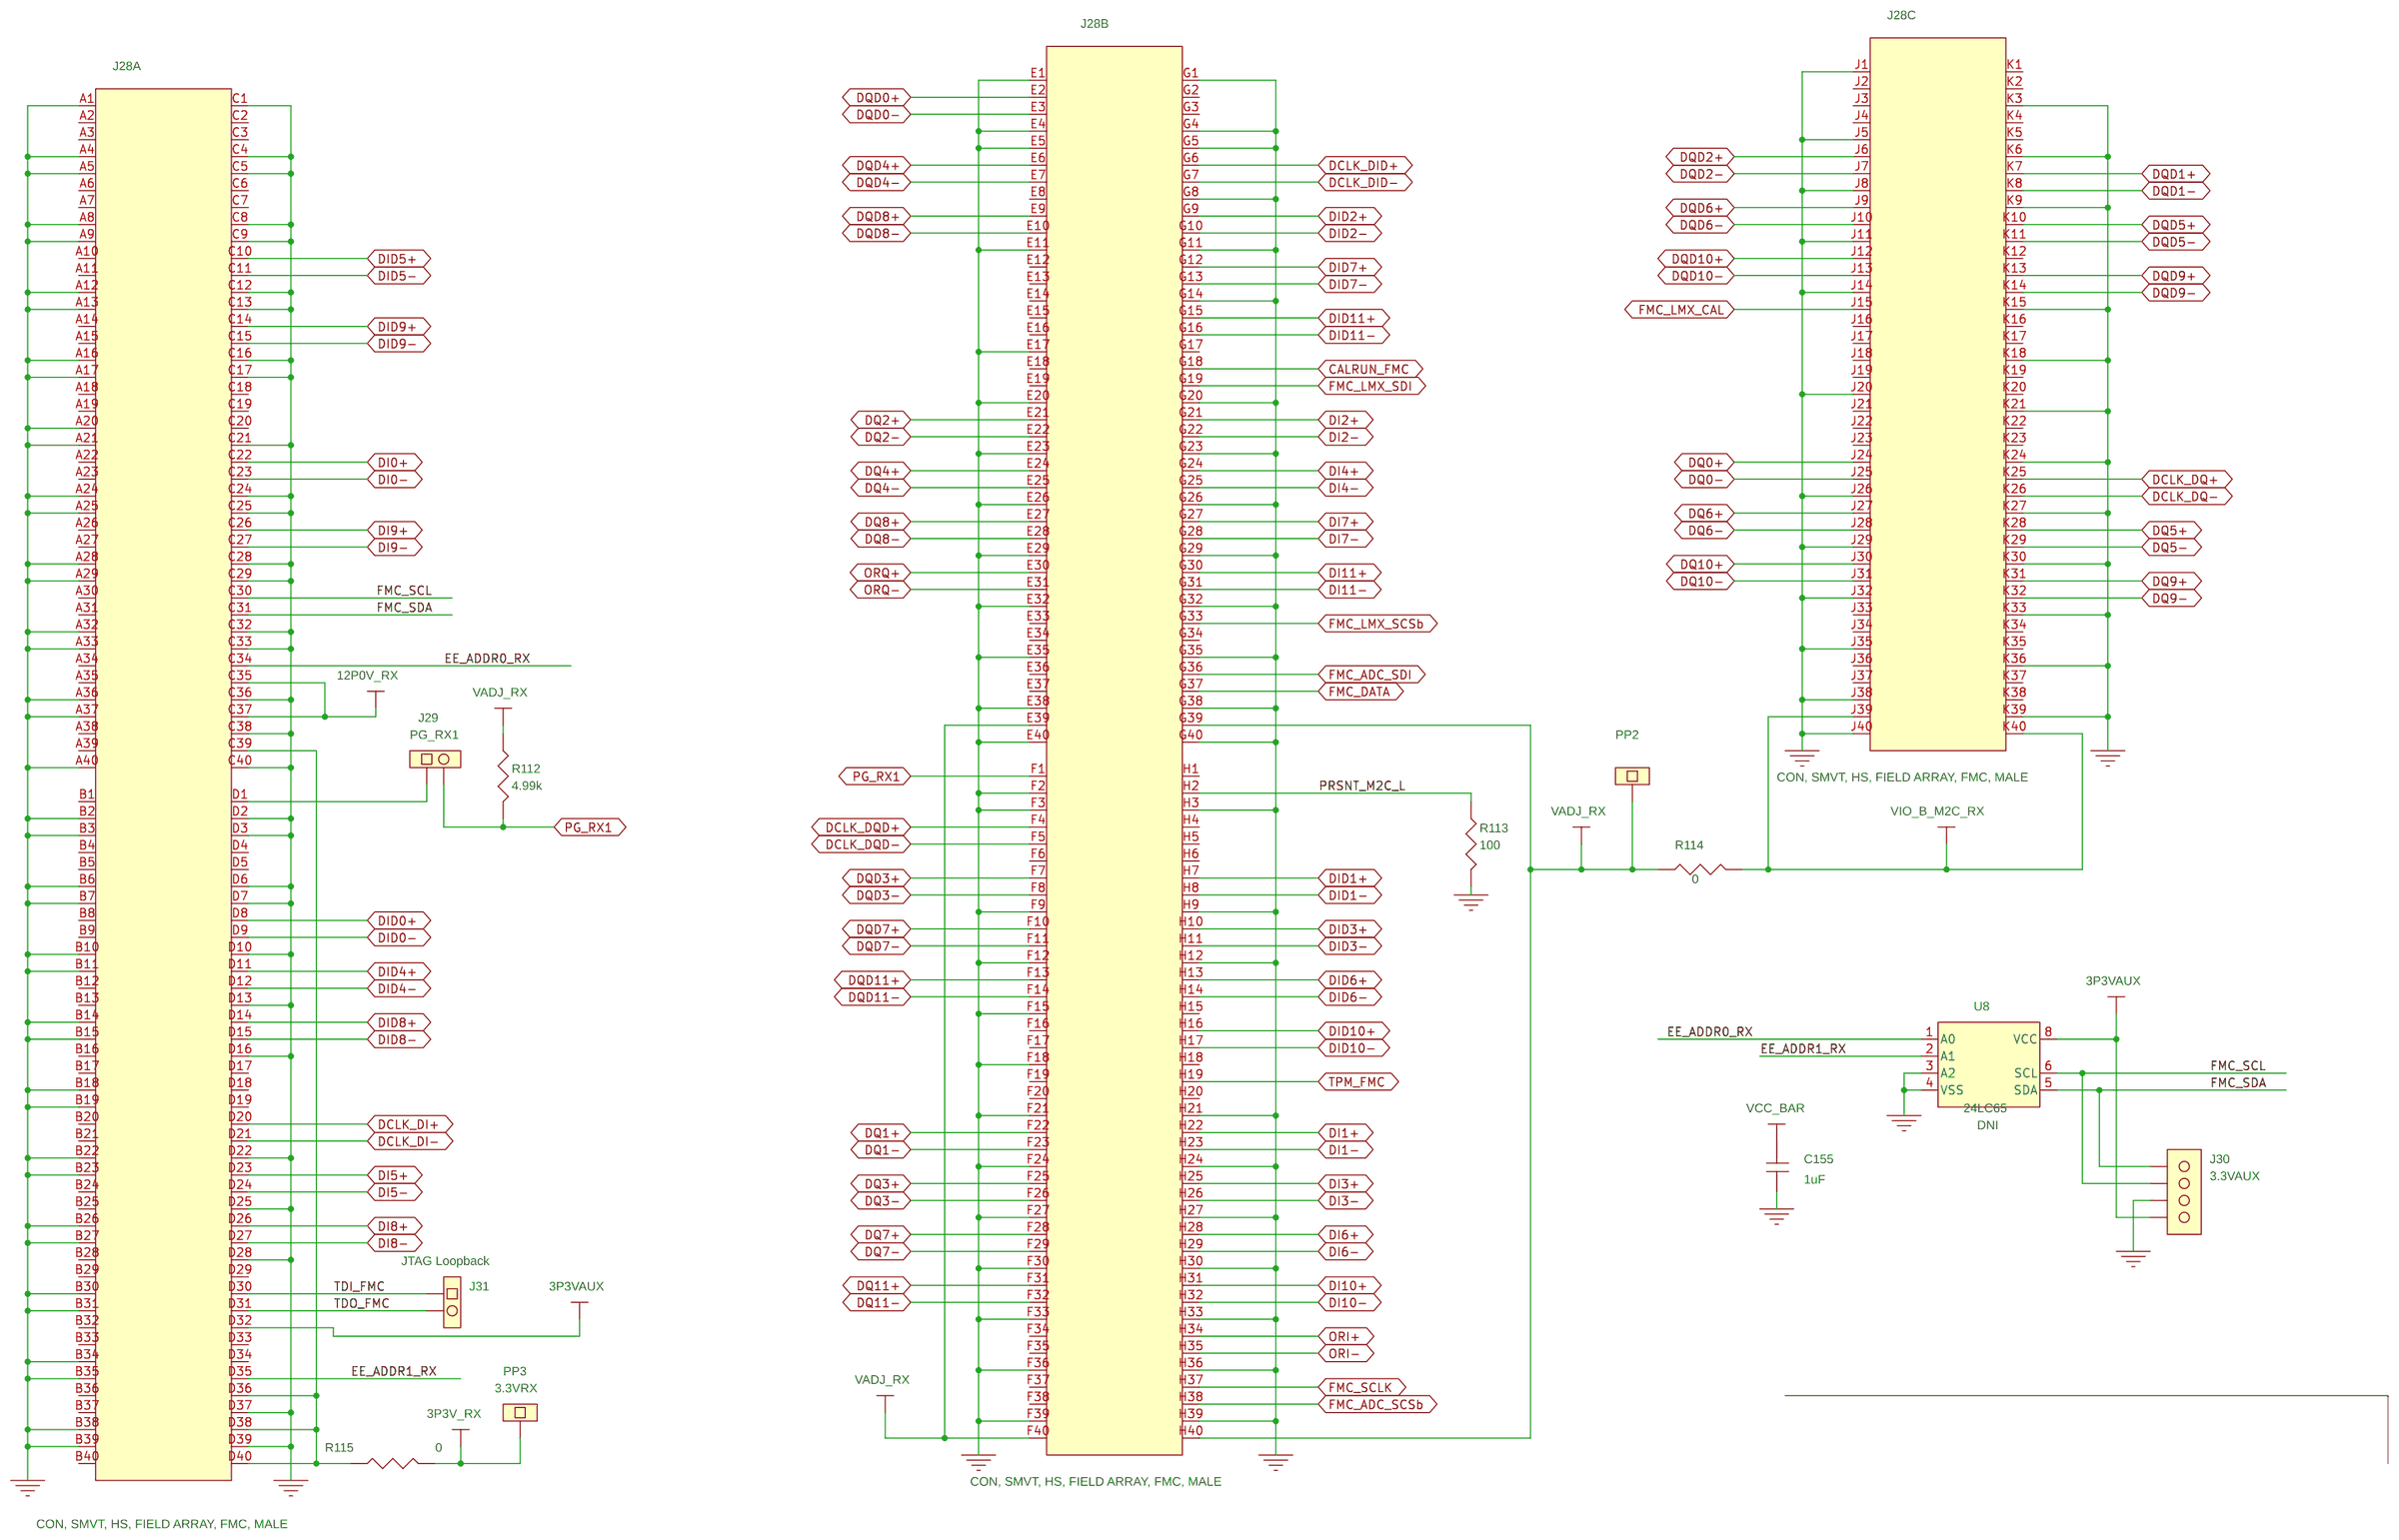
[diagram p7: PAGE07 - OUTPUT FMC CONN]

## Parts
sheet PAGE02 - ADC ANALOG INPUT
C1  .1uF  [0402]
C2  .1uF  [0402]
C3  .01uF  [0201]
C4  1pF  [0402]
C5  2.7pF  [0402]
C6  .1uF  [0402]
C7  1pF  [0402]
C8  2.7pF  [0402]
C9  .01uF  [0306]
C10  2200pF  [0306]
C11  .01uF  [0306]
C12  2200pF  [0306]
C13  .01uF  [0201]
C14  .1uF  [0402]
C15  .01uF  [0402]
C16  .1uF  [0402]
C17  .1uF  [0402]
C18  .01uF  [0201]
C19  1pF  [0402]
C20  2.7pF  [0402]
C21  1pF  [0402]
C22  2.7pF  [0402]
C23  .01uF  [0201]
C24  .1uF  [0402]
C25  .01uF  [0306]
C26  2200pF  [0306]
C27  .01uF  [0306]
C28  2200pF  [0306]
C29  .1uF  [0402]
J1  SMA, THVT, SMT CENTER PIN  [SMA_THVT_SMT_250x250]
J2  SMA, THVT, SMT CENTER PIN  [SMA_THVT_SMT_250x250]
J3  SMA, THVT, SMT CENTER PIN  [SMA_THVT_SMT_250x250]
J4  SMA, THVT, SMT CENTER PIN  [SMA_THVT_SMT_250x250]
J5  SMA, THVT, SMT CENTER PIN  [SMA_THVT_SMT_250x250]
J6  SMA, THVT, SMT CENTER PIN  [SMA_THVT_SMT_250x250]
JP1  JUMPER_1X2_100  [HDR_THVT_1X2_100_M]
JP2  JUMPER_1X2_100  [HDR_THVT_1X2_100_M]
L1  6.8nH  [IND_0603]
L2  3.6nH  [IND_0603]
L3  6.8nH  [IND_0603]
L4  3.6nH  [IND_0603]
L5  6.8nH  [IND_0603]
L6  3.6nH  [IND_0603]
L7  6.8nH  [IND_0603]
L8  3.6nH  [IND_0603]
R1  0  [0402]
R2  200  [0402]
R3  12.1  [0402]
R4  40.2  [0402]
R5  1.1k  [0402]
R6  200  [0402]
R7  12.1  [0402]
R8  1.1k  [0402]
R9  40.2  [0402]
R10  49.9  [0402]
R11  200  [0402]
R12  0  [0402]
R13  10k  [0402]
R14  1k  [0603]
R15  1k  [0603]
R16  0  [0402]
R17  200  [0402]
R18  12.1  [0402]
R19  40.2  [0402]
R20  1.1k  [0402]
R21  49.9  [0402]
R22  200  [0402]
R23  40.2  [0402]
R24  200  [0402]
R25  12.1  [0402]
R26  1.1k  [0402]
R27  0  [0402]
R28  10k  [0402]
U1  LMH5401-SP  [LCCC_14_5p5x6MM_1P27]
U2  LMH5401-SP  [LCCC_14_5p5x6MM_1P27]
sheet PAGE03 - ADC SPI
C30  0.1uF  [0603]
C31  1uF  [0603]
C32  .1uF  [0402]
C33  .1uF  [0402]
C34  100pF  [0402]
C35  .1uF  [0402]
C36  10uF  [TANT_B]
C37  100pF  [0402]
C38  .1uF  [0402]
C39  .1uF  [0402]
C40  4700pF  [0402]
C41  4700pF  [0402]
C42  4700pF  [0402]
C43  4700pF  [0402]
D1  LED ORANGE  [LED_0805]
D2  1N4148W  [DIODE_SM_1N4148W]
D3  LED ORANGE  [LED_0805]
D4  1N4148W  [DIODE_SM_1N4148W]
D5  LED RED  [LED_0805]
J7  HDR, THVT, 2POS, .100, GOLD  [HDR_THVT_1x2_100_M]
J8  HDR, THVT, 2POS, .100, GOLD  [HDR_THVT_1x2_100_M]
J9  HDR, THVT, 2POS, .100, GOLD  [HDR_THVT_1x2_100_M]
J10  HDR, THVT, 2POS, .100, GOLD  [HDR_THVT_1x2_100_M]
J11  HDR, THVT, 2POS, .100, GOLD  [HDR_THVT_1x2_100_M]
J12  HDR, THVT, 2POS, .100, GOLD  [HDR_THVT_1x2_100_M]
J13  SMA, THVT, SMT CENTER PIN  [SMA_THVT_SMT_250x250]
J14  SMA, THVT, SMT CENTER PIN  [SMA_THVT_SMT_250x250]
J15  SMA, THVT, SMT CENTER PIN  [SMA_THVT_SMT_250x250]
J16  SMA, THVT, SMT CENTER PIN  [SMA_THVT_SMT_250x250]
J17  SMA, THVT, SMT CENTER PIN  [SMA_THVT_SMT_250x250]
J18  SMA, THVT, SMT CENTER PIN  [SMA_THVT_SMT_250x250]
J19  SMA, THVT, SMT CENTER PIN  [SMA_THVT_SMT_250x250]
J20  SMA, THVT, SMT CENTER PIN  [SMA_THVT_SMT_250x250]
J21  SMA, THVT, SMT CENTER PIN  [SMA_THVT_SMT_250x250]
JP3  JUMPER_1X3_100  [HDR_THVT_1x3_100_M]
JP4  JUMPER_1X3_100  [HDR_THVT_1x3_100_M]
JP5  JUMPER_1X3_100  [HDR_THVT_1x3_100_M]
JP6  JUMPER_1X3_100  [HDR_THVT_1x3_100_M]
JP7  JUMPER_1X3_100  [HDR_THVT_1x3_100_M]
JP8  JUMPER_1X3_100  [HDR_THVT_1x3_100_M]
JP9  JUMPER_1X3_100  [HDR_THVT_1x3_100_M]
R29  1k  [0402]
R30  1k  [0402]
R31  1M  [0402]
R32  10k  [0402]
R33  10k  [0402]
R34  1.2k  [0402]
R35  1k  [0402]
R36  1M  [0402]
R37  1.2k  [0402]
R38  10k  [0402]
R39  1.3k  [0402]
R40  1k  [0402]
R41  1.3k  [0402]
R42  3.3k  [0402]
R43  0  [0402]
R44  3.3k  [0402]
R45  0  [0402]
R46  1k  [0402]
R47  10k  [0402]
R48  10k  [0402]
R49  750  [0402]
R51  100k  [0402]
R53  100  [0402]
SHN1  SHUNT HEADER
SHN2  SHUNT HEADER
SHN3  SHUNT HEADER
SHN4  SHUNT HEADER
SHN5  SHUNT HEADER
SHN6  SHUNT HEADER
SHN7  SHUNT HEADER
SHN8  SHUNT HEADER
T1  TC1-1-43X+  [TFMR_5_150x150_50]
TP1  ORN  [TP_THVT_100_RND]
TP2  ORN  [TP_THVT_100_RND]
TP3  ORN  [TP_THVT_100_RND]
TP4  ORN  [TP_THVT_100_RND]
U3  LMC6762  [SOIC_8_197x157_50]  (sections A,B)
U5  TMP461-SP  [CFP_10_270x276_50_PWRPAD]
sheet PAGE04 - ADC FMC CONNECTIONS
C44  10uF  [0603]
C45  1uF  [0603]
C46  .1uF  [0201]
C47  .1uF  [0201]
C48  .1uF  [0201]
C49  .1uF  [0201]
C50  .1uF  [0201]
C51  .1uF  [0201]
C52  .1uF  [0201]
C53  0.1uF  [0201]
C54  0.1uF  [0201]
C55  .1uF  [0201]
C56  .1uF  [0201]
C57  0.1uF  [0201]
C58  0.1uF  [0201]
C59  0.1uF  [0201]
C60  0.1uF  [0201]
C61  0.1uF  [0201]
C62  0.1uF  [0201]
JP10  JUMPER_1X3_100  [HDR_THVT_1x3_100_M]
R54  1k  [0201]
R55  1k  [0201]
R56  1k  [0201]
R57  1k  [0201]
R61  120  [0201]
R62  120  [0201]
R64  0  [0201]
R65  0  [0201]
R67  120  [0201]
R68  120  [0201]
R70  100  [0201]
R71  120  [0201]
R72  120  [0201]
R73  0  [0201]
R75  0  [0201]
R77  120  [0201]
R78  120  [0201]
R79  100  [0201]
R80  0  [0201]
R81  0  [0201]
R82  0  [0201]
R83  0  [0201]
R84  0  [0402]
R194  0  [0201]
R195  0  [0201]
R196  0  [0201]
R197  0  [0201]
SHN9  SHUNT HEADER
U6  CDCLVP111-SP  [CQFP_HFG_36_0p635mm]
sheet PAGE05 - ADC PWR
C63  .1uF  [0201]
C64  .1uF  [0201]
C65  .1uF  [0201]
C66  .1uF  [0201]
C67  .1uF  [0201]
C68  .1uF  [0201]
C69  .1uF  [0201]
C70  .1uF  [0201]
C71  .1uF  [0201]
C72  .1uF  [0201]
C73  .1uF  [0201]
C74  .1uF  [0201]
C75  .1uF  [0201]
C76  .1uF  [0201]
C77  10uF  [TANT_B]
C78  .1uF  [0201]
C79  .1uF  [0201]
C80  .1uF  [0201]
C81  .1uF  [0201]
C82  .1uF  [0201]
C83  .1uF  [0201]
C84  .1uF  [0201]
C85  .1uF  [0201]
C86  .1uF  [0201]
C87  .1uF  [0201]
C88  .1uF  [0201]
C89  .1uF  [0201]
C90  .1uF  [0201]
C91  .1uF  [0201]
C92  .1uF  [0201]
C93  .1uF  [0201]
C94  .1uF  [0201]
C95  .1uF  [0201]
C96  10uF  [TANT_B]
C97  .1uF  [0201]
C98  .1uF  [0201]
C99  .1uF  [0201]
C100  .1uF  [0201]
C101  .1uF  [0201]
C102  .1uF  [0201]
C103  .1uF  [0201]
C104  .1uF  [0201]
C105  .1uF  [0201]
C106  .1uF  [0201]
C107  .1uF  [0201]
C108  .1uF  [0201]
C109  .1uF  [0201]
C110  .1uF  [0201]
C111  .1uF  [0201]
C112  .1uF  [0201]
C113  10uF  [TANT_B]
C114  .1uF  [0201]
C115  .1uF  [0201]
C116  .1uF  [0201]
C117  .1uF  [0201]
C118  .1uF  [0201]
C119  .1uF  [0201]
C120  .1uF  [0201]
C121  .1uF  [0201]
C122  .1uF  [0201]
C123  10uF  [TANT_B]
C124  .1uF  [0201]
C125  .1uF  [0201]
C126  .1uF  [0201]
R85  0  [0805]
R86  0  [0805]
R87  0  [0805]
R88  0  [0805]
U4  ADC12DJ1620  [ADC12D1620QML-SP]  (sections A,B,C,D,E,F)
sheet PAGE06 - LMX
C127  10uF  [0603]
C128  .1uF  [0402]
C129  1uF  [0402]
C130  1800pF  [0603]
C131  .068uF  [0603]
C132  390pF  [0603]
C133  .1uF  [0402]
C134  300pF  [0603]
C135  .1uF  [0402]
C136  .1uF  [0402]
C137  .1uF  [0402]
C138  .1uF  [0402]
C139  .1uF  [0402]
C140  .1uF  [0402]
C141  1uF  [0402]
C142  .1uF  [0402]
C143  1uF  [0402]
C144  .1uF  [0402]
C145  1uF  [0402]
C146  1uF  [0402]
C147  1uF  [0402]
C148  1uF  [0402]
C149  1uF  [0402]
C150  10uF  [0603]
C151  10uF  [0603]
C152  10uF  [0603]
C153  10uF  [0603]
C154  10uF  [0603]
D6  LED GREEN  [LED_0805]
J22  SMA, THVT, SMT CENTER PIN  [SMA_THVT_SMT_250x250]
J24  HDR, THVT, 2POS, .100  [HDR_THVT_1x2_100_M]
J26  SMA, THVT, SMT CENTER PIN  [SMA_THVT_SMT_250x250]
J27  SMA, THVT, SMT CENTER PIN  [SMA_THVT_SMT_250x250]
L9  18nH  [IND_0402]
L10  18nH  [IND_0402]
PP1  PROBE POINT  [PROBE_POINT_30PAD]
R89  18  [0402]
R90  0  [0402]
R91  49.9  [0402]
R92  150  [0402]
R93  100  [0402]
R94  150  [0402]
R95  68  [0402]
R96  49.9  [0402]
R97  49.9  [0402]
R98  0  [0402]
R99  49.9  [0402]
R100  49.9  [0402]
R101  0  [0402]
R102  1k  [0402]
R103  0  [0402]
R104  49.9  [0402]
R105  100  [0402]
R106  0  [0402]
R107  330  [0402]
R108  0  [0402]
R109  0  [0402]
R110  10k  [0402]
R111  10k  [0402]
R184  0  [0603]
R185  0  [0603]
TP5  ORN  [TP_THVT_100_RND]
TP6  ORN  [TP_THVT_100_RND]
TP7  ORN  [TP_THVT_100_RND]
TP8  ORN  [TP_THVT_100_RND]
TP9  ORN  [TP_THVT_100_RND]
U7  LMX2615-SP  [CQFP_64_429x429_0p5MM]  (sections A,B)
Y1  100.0000MHz  [OSC_6_SM_SIA0006B]
sheet PAGE07 - OUTPUT FMC CONN
C155  1uF  [0402]
J28  CON, SMVT, HS, FIELD ARRAY, FMC, MALE  [CON_SMVT_40x10_SEAM_MTG]  (sections A,B,C)
J29  HDR, THVT, 2POS, .100, GOLD  [HDR_THVT_1X2_100_M]
J30  HDR, THVT, 4POS, .100, GOLD  [HDR_THVT_1x4_100_M]
J31  HDR, THVT, 2POS, .100, GOLD  [HDR_THVT_1X2_100_M]
PP2  PROBE POINT  [PROBE_POINT_30PAD]
PP3  PROBE POINT  [PROBE_POINT_30PAD]
R112  4.99k  [0402]
R113  100  [0603]
R114  0  [0402]
R115  0  [0402]
U8  24LC65  [SO_8_207x207_50]
sheet PAGE08 - MSP430
C231  10pF  [0402]
C232  10pF  [0402]
C233  .1uF  [0201]
C234  27pF  [0402]
C235  27pF  [0402]
C236  .1uF  [0201]
C237  1uF  [0603]
C238  .001uF  [0402]
D10  LED GREEN  [LED_0805]
J35  HDR, THVT, 2POS, .100, GOLD  [HDR_THVT_1x2_100_M]
J36  HDR, Shrouded, 14 POS STRGHT GOLD  [CON_THVT_2x7_100_M_SHROUDED_KEY]
JP12  JUMPER_1X3_100  [HDR_THVT_1x3_100_M]
JP13  JUMPER_1X3_100  [HDR_THVT_1x3_100_M]
R186  0  [0402]
R187  0  [0402]
R188  390  [0402]
R189  6.81k  [0402]
R190  47k  [0402]
SHN13  SHUNT HEADER
SHN14  SHUNT HEADER
SW1  MSP INP  [sw_thvt_spst_pts635sl43]
SW2  MSP RST  [sw_thvt_spst_pts635sl43]
TP17  ORN  [TP_THVT_100_RND]
TP18  ORN  [TP_THVT_100_RND]
TP19  ORN  [TP_THVT_100_RND]
U20  MSP430FR5969-SP  [qfn_48_281x281_0p50mm_rgz]
U21  LMT01  [LMT01-SP]
U22  LMT01  [LMT01-SP]
Y3  32.768KHZ  [xtal_2_sm_ms3v-t1r_264x55]
Y4  4MHz  [XTAL_HC-49UX]

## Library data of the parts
C1 C2 C6 C14 C16 C17 C24 C29 C136-C138 C140 C142 C144 = CAP_0402_0.1uF_H
C3 C13 C18 C23 = CAP_0201_10000pF: Note: DNI
C4 C7 C19 C21 = CAP_0402_1pF: Mfr_Name: MURATA; Mfr_Part_Number: GJM1555C1H1R0WB01D
C5 C8 C20 C22 = CAP_0402_2.7pF: Mfr_Name: MURATA; Mfr_Part_Number: GRM1555C1H2R7CA01D
C9 C11 C25 C27 = CAP_0306_0.01uF
C10 C12 C26 C28 = CAP_0306_2200pF
C15 = CAP_0402_0.01uF
J1 = SMA_THVT_SMA_CENTER_PIN: TI_Silktext: VINI+
J2 = SMA_THVT_SMA_CENTER_PIN: TI_Silktext: AINI
J3 = SMA_THVT_SMA_CENTER_PIN: TI_Silktext: VINI-
J4 = SMA_THVT_SMA_CENTER_PIN: TI_Silktext: VINQ+
J5 = SMA_THVT_SMA_CENTER_PIN: TI_Silktext: AINQ
J6 = SMA_THVT_SMA_CENTER_PIN: TI_Silktext: VINQ-
JP1 = JUMPER_1X2_100: SILK: AMPI_PD
JP2 = JUMPER_1X2_100: SILK: AMPQ_PD
L1 L3 L5 L7 = IND_0603_H_0: Mfr_Name: COILCRAFT; Mfr_Part_Number: 0603HC-6N8XJLU
L2 L4 L6 L8 = IND_0603_H_0: Mfr_Name: COILCRAFT; Mfr_Part_Number: 0603HC-3N6XJLU
R1 R12 R16 R27 = Res_0201_Zero_H: Mfr_Part_Number: ERJ-2GE0R00X; Note: DNI
R2 R11 R17 R24 = Res_0402_127: Mfr_Part_Number: ERJ-2RKF2000X
R3 R7 R18 R25 = Res_0402_22.6: Mfr_Part_Number: ERJ-2RKF12R1X
R4 R9 R19 R23 = Res_0402_40.2_H
R5 R8 R20 R26 = Res_0603_1.3k_H: Mfr_Part_Number: ERJ-2RKF1101X
R6 R22 = Res_0603_100_H: Mfr_Part_Number: ERJ-2RKF2000X; Note: DNI
R10 R21 R91 R96 = Res_0402_51_.5%: Mfr_Part_Number: ERJ-2RKF49R9X
R13 R28 R32 R33 R38 R47 R48 R110 = Res_0402_10k
R14 R15 = Res_0603_1k
U1 U2 = LMH5401-SP: Mfr_Part_Number: LMH5401FFK/EM
C30 = CAP_0603_0.1uF: Mfr_Part_Number: 0603YC104JAT2A
C31 C45 = CAP_0603_1uF: Mfr_Name: AVX; Mfr_Part_Number: 0603YD105KAT2A
C32 C33 C38 C39 C128 C133 C135 C139 = CAP_0402_4700pF_H: Mfr_Name: MURATA; Mfr_Part_Number: GRM155R71C104KA88D
C34 C37 = CAP_0603_100pF: Mfr_Part_Number: 04025A101JAT2A
C35 = CAP_0603_0.1uF: Mfr_Name: MURATA; Mfr_Part_Number: GRM155R71C104KA88D
C36 C77 C96 C113 C123 = CAP_TANT_B_10uF_10V: Mfr_Name: Vishay Sprague; Mfr_Part_Number: 293D106X0010B2TE3
C40 C43 = CAP_0402_4700pF_H: Mfr_Part_Number: CC0402KRX7R8BB472; Note: DNI
C41 C42 = CAP_0402_4700pF_H
D1 = LED_ORANGE_0603: Mfr_Part_Number: LTST-C170KFKT; SILK: OVRI
D2 D4 = DIODE_1N4148W
D3 = LED_ORANGE_0603: Mfr_Part_Number: LTST-C170KFKT; SILK: OVRQ
D5 = LED_RED_0: TI_SILKTEXT: TEMP
J7 = HEADER_1x2_0: Mfr_Part_Number: HTSW-102-07-G-S; Note: OPEN; TI_SILKTEXT: PDI
J8 = HEADER_1x2_0: Mfr_Part_Number: HTSW-102-07-G-S; Note: OPEN; TI_SILKTEXT: PDQ
J9 = HEADER_1x2_0: Mfr_Part_Number: HTSW-102-07-G-S; Note: OPEN; TI_SILKTEXT: CALTRG
J10 = HEADER_1x2_0: Mfr_Part_Number: HTSW-102-07-G-S; Note: SHUNT 1-2; TI_SILKTEXT: VCMO
J11 = HEADER_1x2_0: Mfr_Part_Number: HTSW-102-07-G-S; Note: DNI; TI_SILKTEXT: TDIODE
J12 = HEADER_1x2_0: Mfr_Part_Number: HTSW-102-07-G-S; Note: OPEN; TI_SILKTEXT: VBG
J13 = SMA_THVT_SMA_CENTER_PIN: TI_Silktext: TMSTP+
J14 = SMA_THVT_SMA_CENTER_PIN: TI_Silktext: RCLK+
J15 = SMA_THVT_SMA_CENTER_PIN: TI_Silktext: RCOUT1+
J16 = SMA_THVT_SMA_CENTER_PIN: TI_Silktext: TMSTP-
J17 = SMA_THVT_SMA_CENTER_PIN: TI_Silktext: RCLK-
J18 = SMA_THVT_SMA_CENTER_PIN: TI_Silktext: RCOUT1-
J19 = SMA_THVT_SMA_CENTER_PIN: TI_Silktext: RCOUT2+
J20 = SMA_THVT_SMA_CENTER_PIN: TI_Silktext: RCOUT2-
J21 = SMA_THVT_SMA_CENTER_PIN: TI_Silktext: DEVCLK+
JP3 = JUMPER_1X3_100: Note: SHUNT 2-3; TI_Silktext: LSPSM
JP4 = JUMPER_1X3_100: Note: SHUNT 2-3; TI_Silktext: TPM
JP5 = JUMPER_1X3_100: Note: SHUNT 2-3; TI_Silktext: NDM
JP6 = JUMPER_1X3_100: Note: SHUNT 2-3; TI_Silktext: FSR
JP7 = JUMPER_1X3_100: Note: SHUNT 2-3; TI_Silktext: DES
JP8 = JUMPER_1X3_100: Note: SHUNT 2-3; TI_Silktext: ECEn
JP9 = JUMPER_1X3_100: Note: SHUNT 2-3; TI_Silktext: DDRPh
R29 R30 R35 R40 R46 R102 = Res_0402_1k
R31 R36 = Res_0402_1M
R34 R37 = Res_0402_1.2k
R39 R41 = Res_0603_1.3k_H: Mfr_Part_Number: ERJ-2RKF1301X
R42 R44 = Res_0402_3.3k_.1%_H: Mfr_Part_Number: ERA-2AEB332X
R43 R45 = Res_0402_Zero_H: Mfr_Part_Number: ERJ-2GE0R00X
R49 = Res_0603_750_H: Mfr_Part_Number: ERJ-2RKF7500X
R51 = Res_0402_100k_H
R53 R105 = Res_0402_100_H
SHN1-SHN7 SHN9 SHN13 SHN14 = SHUNT_HEADER: Mfr_Name: Sullins; Mfr_Part_Number: SPC02SYAN
SHN8 = SHUNT_HEADER: Mfr_Name: Sullins; Mfr_Part_Number: SPC02SYAN; Note: <Note>
T1 = TFMR_5_TC1-1-43X+
TP1 = TESTPOINT_ORANGE: TI_SILKTEXT: CALRUN
TP2 = TESTPOINT_ORANGE: TI_SILKTEXT: VBG
TP3 = TESTPOINT_ORANGE: TI_SILKTEXT: TCRIT2
TP4 = TESTPOINT_ORANGE: TI_SILKTEXT: TCRIT1
U3 = LMC6762: Mfr_Part_Number: LMC6762AIM/NOPB
U5 = TMP461_0: Mfr_Part_Number: TMP461HKU/EM
C44 = CAP0201_0: Mfr_Name: TDK; Mfr_Part_Number: C1608X5R1A106K080AC; TOL: 10%; VOLTAGE: 10V
C46-C52 C55 C56 C63-C76 C78-C95 C97-C112 C114-C122 C124-C126 = CAP0402_0: Mfr_Name: MURATA; Mfr_Part_Number: GRM033R61A104KE15D; TOL: 10%; Voltage: 16V
C53 C54 C57-C62 = CAP_NP_1: Mfr_Name: MURATA; Mfr_Part_Number: GRM033R61A104KE15D; TOL: 10%; VOLTAGE: 16V
JP10 = JUMPER_1X3_100: Note: SHUNT 1-2; TI_Silktext: INPUT_SEL
R54-R57 = Res_0402_1k: Mfr_Name: Samsung; Mfr_Part_Number: RCS0603F102CS
R61 R62 R67 R68 R71 R72 R77 R78 = Res_0402_249: Mfr_Part_Number: ERJ-1GNJ121C
R64 R65 R80 R81 R194-R197 = Res_0603_Zero_H: Mfr_Part_Number: ERJ-1GN0R00C
R70 R79 = Res_0402_100_H: Mfr_Part_Number: ERJ-1GNF1000C
R73 R75 R82 R83 = Res_0603_Zero_H: Mfr_Part_Number: ERJ-1GN0R00C; Note: DNI
R84 R90 R186 R187 = Res_0603_Zero_H: Mfr_Part_Number: ERJ-2GE0R00X
U6 = CDCLVP111-SP: Mfr_Name: Texas Instruments; Mfr_Part_Number: CDCLVP111HFG/EM
R85-R88 = Res_0805_Zero_H: Mfr_Name: KEYSTONE; Mfr_Part_Number: 5106
U4 = ADC12DJ1620-QML
C127 C150-C154 = CAP_NP_1: Mfr_Name: Taiyo Yuden; Mfr_Part_Number: LMK107BBJ106MALT; TOL: 20%; VOLTAGE: 10V
C129 C147 C148 = CAP_NP_0: Mfr_Name: MURATA; Mfr_Part_Number: GRM152R60J105ME15D; TOL: 20%; VOLTAGE: 6.3V
C130 = CAP_NP_0: Mfr_Name: MURATA; Mfr_Part_Number: GRM1885C1H182JA01J; VOLTAGE: 50V
C131 = CAP_NP_0: Mfr_Name: MURATA; Mfr_Part_Number: GCM188R71H683KA57D; TOL: 10%; VOLTAGE: 50V
C132 = CAP_NP_0: Mfr_Name: MURATA; Mfr_Part_Number: GRM1885C1H391GA01D; TOL: 10%; VOLTAGE: 50V
C134 = CAP_NP_0: Mfr_Name: MURATA; Mfr_Part_Number: GRM1885C2A301JA01D; TOL: 10%; VOLTAGE: 100V
C141 C143 C145 C146 C149 = CAP_0402_4700pF_H: Mfr_Name: MURATA; Mfr_Part_Number: GRM152R60J105ME15D; TOL: 20%; VOLTAGE: 6.3V
D6 = LED: Mfr_Name: LITE ON; Mfr_Part_Number: LTST-C170KGKT; TI_Silktext: MUXout
J22 = SMA_THVT_SMA_CENTER_PIN: TI_Silktext: LMX_REF
J24 = HEADER_1x2_0: Note: OPEN; TI_SILKTEXT: OSC_OE
J26 = SMA_THVT_SMA_CENTER_PIN: TI_Silktext: RFOUTBP
J27 = SMA_THVT_SMA_CENTER_PIN: TI_Silktext: RFOUTBN
L9 L10 = IND_0402_H_0: Mfr_Name: MURATA; Mfr_Part_Number: LQG15HS18NJ02D
PP1 = PROBE_POINT_0: Mfr_Name: HARWIN; Mfr_Part_Number: P1113SS3; Note: SMD PAD; TI_Silktext: SYNC
R89 = Res_0603_Zero_H: Mfr_Part_Number: ERJ-2RKF18R0X
R92 R94 = Res_0603_Zero_H: Mfr_Part_Number: ERJ-2RKF1500X
R93 = Res_0402_100_H: Note: DNI
R95 = Res_0402_68
R97 R99 R100 R104 = Res_0402_49.9
R98 R101 R103 R106 R108 R109 = Res_0402_Zero_H
R107 = Res_0402_330
R111 = Res_0402_10k: Note: DNI
R184 R185 = Res_0402_Zero_H: Mfr_Part_Number: ERJ-3GEY0R00V
TP5 = TESTPOINT_ORANGE: TI_SILKTEXT: VTUNE
TP6 = TESTPOINT_ORANGE: TI_SILKTEXT: LMX_CLK
TP7 = TESTPOINT_ORANGE: TI_SILKTEXT: LMX_DATA
TP8 = TESTPOINT_ORANGE: TI_SILKTEXT: LMX_CSB
TP9 = TESTPOINT_ORANGE: TI_SILKTEXT: MUX_OUT
U7 = LMX2615-SP
Y1 = OSC_6_SM_VECTRON_VC-708_0: Mfr_Name: Texas Instruments; Mfr_Part_Number: LMK62E2-100M00SIAT
C155 = CAP_NP_1: Mfr_Name: YAGEO; Mfr_Part_Number: CC0402MRX5R6BB105; TOL: 20%; VOLTAGE: 6.3V
J28 = CON_SMVT_40X10_SEAM
J29 = JUMPER_1X2_100: SILK: PG_RX1
J30 = HEADER_1x4_100: TI_SILKTEXT: 3.3VAUX
J31 = JUMPER_1X2_100: SILK: JTAG Loopback
PP2 = PROBE_POINT_0: Mfr_Name: HARWIN; Mfr_Part_Number: P1113SS3; TI_Silktext: VADJ_RX
PP3 = PROBE_POINT_0: Mfr_Name: HARWIN; Mfr_Part_Number: P1113SS3; TI_Silktext: 3.3VRX
R112 = Res_0402_4.99K
R113 = Res_0201_100: Mfr_Part_Number: ERJ-3EKF1000V
R114 R115 = Res_0402_Zero: Mfr_Part_Number: ERJ-2GE0R00X
U8 = 24LC65: Mfr_Name: MICROCHIP TECHNOLOGY; Mfr_Part_Number: 24C65T-I/SM; Note: DNI
C231 = CAP_0402_18pF
C232 = CAP_0402_18pF: Mfr_Part_Number: 04025U100CAT2A
C233 C236 = CAP_0201_0.1uF: Mfr_Name: MURATA; Mfr_Part_Number: GRM033R61A104KE15D
C234 C235 = CAP_0402_18pF: Mfr_Part_Number: 04025A270FAT2A; Note: DNI
C237 = CAP_0603_1uF
C238 = CAP_0402_0.001uF_H
D10 = LED: Mfr_Name: LITE ON; Mfr_Part_Number: LTST-C170KGKT; TI_Silktext: MSP_STAT
J35 = HEADER_1x2_0: Mfr_Part_Number: HTSW-102-07-G-S; Note: OPEN; TI_SILKTEXT: TS MSP
J36 = HEADER_2x7_100: Mfr_Name: 3M; Mfr_Part_Number: N2514-6002-RB; TI_SILKTEXT: JTAG
JP12 = JUMPER_1X3_100: Note: SHUNT 1-2; TI_Silktext: TS1 SEL
JP13 = JUMPER_1X3_100: Note: SHUNT 1-2; TI_Silktext: TS2 SEL
R188 = Res_0402_330: Mfr_Part_Number: ERJ-2RKF3900X
R189 = Res_0402_4.99K: Mfr_Part_Number: ERJ-2RKF6811X
R190 = R_0: Mfr_Name: Panasonic; Mfr_Part_Number: ERJ-2RKF4702X; TOL: 1%
SW1 SW2 = SW_PUSHBUTTON: Mfr_Name: C&K Components; Mfr_Part_Number: PTS635SL43 LFS
TP17 = TESTPOINT_ORANGE: TI_SILKTEXT: TS PLSE
TP18 TP19 = TESTPOINT_ORANGE
U20 = MSP430FR5969-SP
U21 U22 = LMT01
Y3 = CRYSTAL_ABM3_0: Mfr_Name: Micro Crystal; Mfr_Part_Number: MS3V-T1R 32.768KHZ 7PF +/-20PPM TA QC
Y4 = CRYSTAL_ABM3_0: Mfr_Name: ECS; Mfr_Part_Number: ECS-40-20-1X; Note: DNI

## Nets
1V9A: C78.1 C79.1 C80.1 C81.1 C82.1 C83.1 C84.1 C85.1 C86.1 C87.1 C88.1 C89.1 C90.1 C91.1 C92.1 C93.1 C94.1 C95.1 C96.1 R85.2 U4.A2(VA) U4.A6(VA) U4.B6(VA) U4.C7(VA) U4.D1(VA) U4.D8(VA) U4.D9(VA) U4.E1(VA) U4.F1(VA) U4.H4(VA) U4.N4(VA) U4.R1(VA) U4.T1(VA) U4.U8(VA) U4.U9(VA) U4.W6(VA) U4.Y2(VA) U4.Y6(VA)
1V9DR: C97.1 C98.1 C99.1 C100.1 C101.1 C102.1 C103.1 C104.1 C105.1 C106.1 C107.1 C108.1 C109.1 C110.1 C111.1 C112.1 C113.1 R87.2 U4.A11(VDR) U4.A15(VDR) U4.C18(VDR) U4.D11(VDR) U4.D15(VDR) U4.D17(VDR) U4.J17(VDR) U4.J20(VDR) U4.R17(VDR) U4.R20(VDR) U4.T17(VDR) U4.U11(VDR) U4.U15(VDR) U4.U16(VDR) U4.Y11(VDR) U4.Y15(VDR)
1V9E: C117.1 C118.1 C119.1 C120.1 C121.1 C122.1 C123.1 R86.2 U4.A8(VE) U4.B9(VE) U4.C8(VE) U4.V8(VE) U4.W9(VE) U4.Y8(VE)
1V9TC: C63.1 C64.1 C65.1 C66.1 C67.1 C68.1 C69.1 C70.1 C71.1 C72.1 C73.1 C74.1 C75.1 C76.1 C77.1 R88.2 U4.G1(VTC) U4.G3(VTC) U4.G4(VTC) U4.H2(VTC) U4.J3(VTC) U4.K3(VTC) U4.L3(VTC) U4.M3(VTC) U4.N2(VTC) U4.P1(VTC) U4.P3(VTC) U4.P4(VTC) U4.R3(VTC) U4.R4(VTC)
+2.5V: C44.1 C45.1 C46.2 C47.2 C48.2 C49.2 C50.2 C51.2 C52.2 C55.2 C56.2 JP10.1(Pin1) U6.1(VCC) U6.9(VCC) U6.10(VCC) U6.17(VCC) U6.18(VCC) U6.27(VCC) U6.28(VCC) U6.35(VCC) U6.36(VCC) ; also on sheet 11
+3.3V_LMX: C127.1 C129.2 C133.2 R98.1 R101.1 R103.1 R106.1 R108.1 R109.1 R110.1 Y1.6(VDD) ; also on sheet 11
+3.3V_LMXRF: L9.2 L10.2 ; also on sheet 11
+4.8V_LMH: C9.1 C10.1 C11.1 C12.1 C25.1 C26.1 C27.1 C28.1 JP1.1 JP2.1 R14.1 U1.1(VS+) U1.10(VS+) U2.1(VS+) U2.10(VS+) ; also on sheet 11
GND: C4.2 C7.1 C9.2 C10.2 C11.2 C12.2 C15.2 C19.2 C21.1 C25.2 C26.2 C27.2 C28.2 C30.2 C31.2 C34.2 C35.2 C36.2 C38.1 C39.1 C44.2 C45.2 C46.1 C47.1 C48.1 C49.1 C50.1 C51.1 C52.1 C55.1 C56.1 C63.2 C64.2 C65.2 C66.2 C67.2 C68.2 C69.2 C70.2 C71.2 C72.2 C73.2 C74.2 C75.2 C76.2 C77.2 C78.2 C79.2 C80.2 C81.2 C82.2 C83.2 C84.2 C85.2 C86.2 C87.2 C88.2 C89.2 C90.2 C91.2 C92.2 C93.2 C94.2 C95.2 C96.2 C97.2 C98.2 C99.2 C100.2 C101.2 C102.2 C103.2 C104.2 C105.2 C106.2 C107.2 C108.2 C109.2 C110.2 C111.2 C112.2 C113.2 C114.2 C115.2 C116.2 C117.2 C118.2 C119.2 C120.2 C121.2 C122.2 C123.2 C124.2 C125.2 C126.2 C127.2 C129.1 C130.2 C132.2 C133.1 C134.2 C137.2 C139.2 C141.2 C142.2 C143.2 C145.2 C146.2 C147.1 C148.1 C149.2 C150.2 C151.1 C152.1 C153.1 C154.1 C155.1 C236.2 C237.2 C238.2 D6.2(CATHODE) D10.2(CATHODE) J1.2(SHIELD1) J1.3(SHIELD2) J1.4(SHIELD3) J1.5(SHIELD4) J2.2(SHIELD1) J2.3(SHIELD2) J2.4(SHIELD3) J2.5(SHIELD4) J3.2(SHIELD1) J3.3(SHIELD2) J3.4(SHIELD3) J3.5(SHIELD4) J4.2(SHIELD1) J4.3(SHIELD2) J4.4(SHIELD3) J4.5(SHIELD4) J5.2(SHIELD1) J5.3(SHIELD2) J5.4(SHIELD3) J5.5(SHIELD4) J6.2(SHIELD1) J6.3(SHIELD2) J6.4(SHIELD3) J6.5(SHIELD4) J10.1 J13.2(SHIELD1) J13.3(SHIELD2) J13.4(SHIELD3) J13.5(SHIELD4) J14.2(SHIELD1) J14.3(SHIELD2) J14.4(SHIELD3) J14.5(SHIELD4) J15.2(SHIELD1) J15.3(SHIELD2) J15.4(SHIELD3) J15.5(SHIELD4) J16.2(SHIELD1) J16.3(SHIELD2) J16.4(SHIELD3) J16.5(SHIELD4) J17.2(SHIELD1) J17.3(SHIELD2) J17.4(SHIELD3) J17.5(SHIELD4) J18.2(SHIELD1) J18.3(SHIELD2) J18.4(SHIELD3) J18.5(SHIELD4) J19.2(SHIELD1) J19.3(SHIELD2) J19.4(SHIELD3) J19.5(SHIELD4) J20.2(SHIELD1) J20.3(SHIELD2) J20.4(SHIELD3) J20.5(SHIELD4) J21.2(SHIELD1) J21.3(SHIELD2) J21.4(SHIELD3) J21.5(SHIELD4) J22.2(SHIELD1) J22.3(SHIELD2) J22.4(SHIELD3) J22.5(SHIELD4) J24.2 J26.2(SHIELD1) J26.3(SHIELD2) J26.4(SHIELD3) J26.5(SHIELD4) J27.2(SHIELD1) J27.3(SHIELD2) J27.4(SHIELD3) J27.5(SHIELD4) J28.A1 J28.A4 J28.A5 J28.A8 J28.A9 J28.A12 J28.A13 J28.A16 J28.A17 J28.A20 J28.A21 J28.A24 J28.A25 J28.A28 J28.A29 J28.A32 J28.A33 J28.A36 J28.A37 J28.A40 J28.B2 J28.B3 J28.B6 J28.B7 J28.B10 J28.B11 J28.B14 J28.B15 J28.B18 J28.B19 J28.B22 J28.B23 J28.B26 J28.B27 J28.B30 J28.B31 J28.B34 J28.B35 J28.B38 J28.B39 J28.C1 J28.C4 J28.C5 J28.C8 J28.C9 J28.C12 J28.C13 J28.C16 J28.C17 J28.C21 J28.C24 J28.C25 J28.C28 J28.C29 J28.C32 J28.C33 J28.C36 J28.C38 J28.C40 J28.D2 J28.D3 J28.D6 J28.D7 J28.D10 J28.D13 J28.D16 J28.D22 J28.D25 J28.D28 J28.D37 J28.D39 J28.E1 J28.E4 J28.E5 J28.E11 J28.E17 J28.E20 J28.E23 J28.E26 J28.E29 J28.E32 J28.E35 J28.E38 J28.E40 J28.F2 J28.F3 J28.F9 J28.F12 J28.F15 J28.F18 J28.F21 J28.F24 J28.F27 J28.F30 J28.F33 J28.F36 J28.F39 J28.G1 J28.G4 J28.G5 J28.G8 J28.G11 J28.G14 J28.G20 J28.G23 J28.G26 J28.G29 J28.G32 J28.G35 J28.G38 J28.G40 J28.H3 J28.H9 J28.H12 J28.H21 J28.H24 J28.H27 J28.H30 J28.H33 J28.H36 J28.H39 J28.J1 J28.J5 J28.J8 J28.J11 J28.J14 J28.J20 J28.J26 J28.J29 J28.J32 J28.J35 J28.J38 J28.J40 J28.K3 J28.K6 J28.K9 J28.K15 J28.K18 J28.K21 J28.K24 J28.K27 J28.K30 J28.K33 J28.K36 J28.K39 J30.3 J36.9 JP3.3(Pin3) JP4.3(Pin3) JP5.3(Pin3) JP6.3(Pin3) JP7.3(Pin3) JP8.3(Pin3) JP9.3(Pin3) R5.2 R8.2 R10.2 R13.2 R15.2 R20.2 R21.2 R26.2 R28.2 R32.2 R33.2 R34.2 R37.2 R38.2 R51.2 R61.2 R62.2 R67.2 R68.2 R71.2 R72.2 R77.2 R78.2 R84.2 R91.2 R92.1 R94.1 R95.2 R96.2 R102.2 R111.2 R113.2 R186.1 R189.2 SW1.1 SW2.1 T1.4(primary) U1.3(VS-) U1.8(VS-) U1.11(GND) U1.14(GND) U1.15(PWRPAD) U2.3(VS-) U2.8(VS-) U2.11(GND) U2.14(GND) U2.15(PWRPAD) U3.4(V-) U4.A1(GND) U4.A7(GND) U4.A9(GNDE) U4.A13(GNDDR) U4.A17(GNDDR) U4.A20(GNDDR) U4.AA2(GND) U4.AA3(GND) U4.AA4(GND) U4.AA5(GND) U4.AA6(GND) U4.AA7(GND) U4.AA8(GND) U4.AA9(GND) U4.AA10(GND) U4.AA11(GND) U4.AB1(GND) U4.AB2(GND) U4.AB3(GND) U4.AB4(GND) U4.AB5(GND) U4.AB6(GND) U4.AB7(GND) U4.AB8(GND) U4.AB9(GND) U4.AB10(GND) U4.AB11(GND) U4.AC1(GND) U4.AC2(GND) U4.AC3(GND) U4.AC4(GND) U4.AC5(GND) U4.AC6(GND) U4.AC7(GND) U4.AC8(GND) U4.AC9(GND) U4.AC10(GND) U4.AC11(GND) U4.AD1(GND) U4.AD2(GND) U4.AD3(GND) U4.AD4(GND) U4.AD5(GND) U4.AD6(GND) U4.AD7(GND) U4.AD8(GND) U4.AD9(GND) U4.AD10(GND) U4.AD11(GND) U4.AE1(GND) U4.AE2(GND) U4.AE3(GND) U4.AE4(GND) U4.AE5(GND) U4.AE6(GND) U4.AE7(GND) U4.AE8(GND) U4.AE9(GND) U4.AE10(GND) U4.AE11(GND) U4.AF1(GND) U4.AF2(GND) U4.AF3(GND) U4.AF4(GND) U4.AF5(GND) U4.AF6(GND) U4.AF7(GND) U4.AF8(GND) U4.AF9(GND) U4.AF10(GND) U4.AF11(GND) U4.AG1(GND) U4.AG2(GND) U4.AG3(GND) U4.AG4(GND) U4.AG5(GND) U4.AG6(GND) U4.AG7(GND) U4.AG8(GND) U4.AG9(GND) U4.AG10(GND) U4.AG11(GND) U4.AH1(GND) U4.AH2(GND) U4.AH3(GND) U4.AH4(GND) U4.AH5(GND) U4.AH6(GND) U4.AH7(GND) U4.AH8(GND) U4.AH9(GND) U4.AH10(GND) U4.AH11(GND) U4.AJ1(GND) U4.AJ2(GND) U4.AJ3(GND) U4.AJ4(GND) U4.AJ5(GND) U4.AJ6(GND) U4.AJ7(GND) U4.AJ8(GND) U4.AJ9(GND) U4.AJ10(GND) U4.AJ11(GND) U4.AK1(GND) U4.AK2(GND) U4.AK3(GND) U4.AK4(GND) U4.AK5(GND) U4.AK6(GND) U4.AK7(GND) U4.AK8(GND) U4.AK9(GND) U4.AK10(GND) U4.AK11(GND) U4.AL1(GND) U4.AL2(GND) U4.AL3(GND) U4.AL4(GND) U4.AL5(GND) U4.AL6(GND) U4.AL7(GND) U4.AL8(GND) U4.AL9(GND) U4.AL10(GND) U4.AL11(GND) U4.B2(GND) U4.B7(GND) U4.B8(GNDE) U4.C6(GND) U4.C9(GNDE) U4.D4(GND) U4.D5(GND) U4.D13(GNDDR) U4.D16(GNDDR) U4.E4(GND) U4.E17(GNDDR) U4.F2(GNDTC) U4.F17(GNDDR) U4.F20(GNDDR) U4.G2(GNDTC) U4.H3(GNDTC) U4.J2(GNDTC) U4.K1(GND) U4.K4(GNDTC) U4.L1(GND) U4.L4(GNDTC) U4.M2(GNDTC) U4.M17(GNDDR) U4.M20(GNDDR) U4.N3(GNDTC) U4.P2(GNDTC) U4.R2(GNDTC) U4.T2(GNDTC) U4.T3(GNDTC) U4.T4(GND) U4.U1(GNDTC) U4.U4(GND) U4.U5(GND) U4.U13(GNDDR) U4.U17(GNDDR) U4.V9(GNDE) U4.V18(GNDDR) U4.W2(GND) U4.W7(GND) U4.W8(GNDE) U4.Y1(GND) U4.Y7(GND) U4.Y9(GNDE) U4.Y13(GNDDR) U4.Y17(GNDDR) U4.Y20(GNDDR) U5.5(A0) U5.6(GND) U5.11(PAD) U6.37(THERMPAD) U7.3(FS0) U7.4(FS1) U7.6(GND) U7.8(GND) U7.10(GND) U7.15(FS2) U7.16(FS3) U7.17(FS4) U7.18(FS5) U7.19(FS6) U7.20(FS7) U7.23(GND) U7.24(GND) U7.28(GND) U7.31(GND) U7.35(GND) U7.38(GND) U7.40(GND) U7.43(SysRefReg) U7.51(GND) U7.54(GND) U7.60(GND) U7.61(GND) U7.65(PWRPAD) U8.3(A2) U8.4(VSS) U20.36(DVSS) U20.49(THERMPAD) Y1.3(GND) ; also on sheet 9 10 11 12
VDDD33: C30.1 C31.1 C34.1 C35.1 C36.1 C236.1 C237.1 D5.1(ANODE) J36.4 JP12.3(Pin3) JP13.3(Pin3) R39.1 R41.1 R47.1 R48.1 R187.1 R190.1 U3.8(V+) U5.1(V+) U5.10(A1) U20.37(DVCC) ; also on sheet 9 11
VDDL19: J12.1 JP3.1(Pin1) JP4.1(Pin1) JP5.1(Pin1) JP6.1(Pin1) JP7.1(Pin1) JP8.1(Pin1) JP9.1(Pin1) R29.1 R30.1 R35.1 ; also on sheet 9 10
VEE: JP10.3(Pin3) R84.1 U6.8(VEE)
VINI+: C2.2 R1.2 U4.H1(VinI+)
VINI-: C14.2 R12.2 U4.J1(VinI-)
VINQ+: C24.2 R27.2 U4.N1(VinQ+)
VINQ-: C17.2 R16.2 U4.M1(VinQ-)
3P3V_RX: PP3.1 R115.2
3P3VAUX: C155.2 J28.D32 J30.4 U8.8(VCC)
12P0V_RX: J28.C35 J28.C37
/CS: U20.39(P2.3/TA0.0) ; also on sheet 9
/RST: C238.1 J36.11 R190.2 SW2.2 U20.23(~{RST}/NMI/SBWTDIO)
ADC_CLK: U4.C5(SCLK) ; also on sheet 9
ADC_SCSb: U4.C4(\\~{SCS}) ; also on sheet 9
ADC_SDI: U4.B4(SDI) ; also on sheet 9
ADC_SDO: U4.A3(SDO) ; also on sheet 9
AIN: C1.2 R3.1
AINI: C1.1 J2.1(CENTER) R5.1
AINQ: C29.1 J5.1(CENTER) R26.1
AIP: C6.2 R7.1
AQN: C16.2 R18.1
AQP: C29.2 R25.1
CALRUN: R40.1 TP1.1(TP) U4.B5(CalRun)
CALRUN_FMC: J28.G18 R40.2
CALTRG: J9.2 R38.1 U4.D6(CAL)
CLK+: C40.1 R53.2 T1.3(secondary)
CLK-: C43.1 R53.1 T1.1(secondary_dot)
CLKN: C42.2 C43.2 U4.V1(CLK-)
CLKP: C40.2 C41.2 U4.U2(CLK+)
CPout: C131.1 C132.1 R90.1 U7.22(CPout)
DCLK_DI+: C59.2 J28.D20 R195.2
DCLK_DI-: C60.2 J28.D21 R194.2
DCLK_DID+: C57.2 J28.G6
DCLK_DID-: C58.2 J28.G7
DCLK_DQ+: C61.2 J28.K25 R197.1
DCLK_DQ-: C62.2 J28.K26 R196.1
DCLK_DQD+: C53.2 J28.F4
DCLK_DQD-: C54.2 J28.F5
DCLK_RST+: J13.1(CENTER) U4.V2(DCLK_RST+)
DCLK_RST-: J16.1(CENTER) U4.W1(DCLK_RST-)
DCLKI+: R64.2 R73.2 U4.K19(DCLKI+)
DCLKI-: R65.2 R75.2 U4.K20(DCLKI-)
DCLKIN: R65.1 R194.1
DCLKIP: R64.1 R195.1
DCLKQ+: R80.2 R82.2 U4.L19(DCLKQ+)
DCLKQ-: R81.2 R83.2 U4.L20(DCLKQ-)
DCLKQN: R81.1 R196.2
DCLKQP: R80.1 R197.2
DDRPh: JP9.2(Pin2) U4.W4(DDRPh)
DES: JP7.2(Pin2) U4.V5(DES)
DEVCLKIN: J21.1(CENTER) T1.6(primary_dot)
DI0+: J28.C22 U4.B18(DI0)
DI0-: J28.C23 U4.C17(DI0-)
DI1+: J28.H22 U4.B19(DI1+)
DI1-: J28.H23 U4.B20(DI1-)
DI2+: J28.G21 U4.C19(DI2+)
DI2-: J28.G22 U4.C20(DI2-)
DI3+: J28.H25 U4.D18(DI3+)
DI3-: J28.H26 U4.E18(DI3-)
DI4+: J28.G24 U4.D19(DI4+)
DI4-: J28.G25 U4.D20(DI4-)
DI5+: J28.D23 U4.E19(DI5+)
DI5-: J28.D24 U4.E20(DI5-)
DI6+: J28.H28 U4.F18(DI6+)
DI6-: J28.H29 U4.F19(DI6-)
DI7+: J28.G27 U4.G17(DI7+)
DI7-: J28.G28 U4.G18(DI7-)
DI8+: J28.D26 U4.G19(DI8+)
DI8-: J28.D27 U4.G20(DI8-)
DI9+: J28.C26 U4.H17(DI9+)
DI9-: J28.C27 U4.H18(DI9-)
DI10+: J28.H31 U4.H19(DI10+)
DI10-: J28.H32 U4.H20(DI10-)
DI11+: J28.G30 U4.J18(DI11+)
DI11-: J28.G31 U4.J19(DI11-)
DID0+: J28.D8 U4.A10(DId0+)
DID0-: J28.D9 U4.B10(DId0-)
DID1+: J28.H7 U4.C10(DId1+)
DID1-: J28.H8 U4.D10(DId1-)
DID2+: J28.G9 U4.B11(DId2+)
DID2-: J28.G10 U4.C11(DId2-)
DID3+: J28.H10 U4.A12(DId3+)
DID3-: J28.H11 U4.B12(DId3-)
DID4+: J28.D11 U4.C12(DId4+)
DID4-: J28.D12 U4.D12(DId4-)
DID5+: J28.C10 U4.B13(DId5+)
DID5-: J28.C11 U4.C13(DId5-)
DID6+: J28.H13 U4.A14(DId6+)
DID6-: J28.H14 U4.B14(DId6-)
DID7+: J28.G12 U4.C14(DId7+)
DID7-: J28.G13 U4.D14(DId7-)
DID8+: J28.D14 U4.B15(DId8+)
DID8-: J28.D15 U4.C15(DId8-)
DID9+: J28.C14 U4.A16(DId9+)
DID9-: J28.C15 U4.B16(DId9-)
DID10+: J28.H16 U4.B17(DId10+)
DID10-: J28.H17 U4.C16(DId10-)
DID11+: J28.G15 U4.A18(DId11+)
DID11-: J28.G16 U4.A19(DId11-)
DQ0+: J28.J24 U4.W18(DQ0+)
DQ0-: J28.J25 U4.V17(DQ0-)
DQ1+: J28.F22 U4.W19(DQ1+)
DQ1-: J28.F23 U4.W20(DQ1-)
DQ2+: J28.E21 U4.V19(DQ2+)
DQ2-: J28.E22 U4.V20(DQ2-)
DQ3+: J28.F25 U4.U18(DQ3+)
DQ3-: J28.F26 U4.T18(DQ3-)
DQ4+: J28.E24 U4.U19(DQ4+)
DQ4-: J28.E25 U4.U20(DQ4-)
DQ5+: J28.K28 U4.T19(DQ5+)
DQ5-: J28.K29 U4.T20(DQ5-)
DQ6+: J28.J27 U4.R18(DQ6+)
DQ6-: J28.J28 U4.R19(DQ6-)
DQ7+: J28.F28 U4.P17(DQ7+)
DQ7-: J28.F29 U4.P18(DQ7-)
DQ8+: J28.E27 U4.P19(DQ8+)
DQ8-: J28.E28 U4.P20(DQ8-)
DQ9+: J28.K31 U4.N17(DQ9+)
DQ9-: J28.K32 U4.N18(DQ9-)
DQ10+: J28.J30 U4.N19(DQ10+)
DQ10-: J28.J31 U4.N20(DQ10-)
DQ11+: J28.F31 U4.M18(DQ11+)
DQ11-: J28.F32 U4.M19(DQ11-)
DQD0+: J28.E2 U4.Y10(DQd0+)
DQD0-: J28.E3 U4.W10(DQd0-)
DQD1+: J28.K7 U4.V10(DQd1+)
DQD1-: J28.K8 U4.U10(DQd1-)
DQD2+: J28.J6 U4.W11(DQd2+)
DQD2-: J28.J7 U4.V11(DQd2-)
DQD3+: J28.F7 U4.Y12(DQd3+)
DQD3-: J28.F8 U4.W12(DQd3-)
DQD4+: J28.E6 U4.V12(DQd4+)
DQD4-: J28.E7 U4.U12(DQd4-)
DQD5+: J28.K10 U4.W13(DQd5+)
DQD5-: J28.K11 U4.V13(DQd5-)
DQD6+: J28.J9 U4.Y14(DQd6+)
DQD6-: J28.J10 U4.W14(DQd6-)
DQD7+: J28.F10 U4.V14(DQd7+)
DQD7-: J28.F11 U4.U14(DQd7-)
DQD8+: J28.E9 U4.W15(DQd8+)
DQD8-: J28.E10 U4.V15(DQd8-)
DQD9+: J28.K13 U4.Y16(DQd9+)
DQD9-: J28.K14 U4.W16(DQd9-)
DQD10+: J28.J12 U4.W17(DQd10+)
DQD10-: J28.J13 U4.V16(DQd10-)
DQD11+: J28.F13 U4.Y18(DQd11+)
DQD11-: J28.F14 U4.Y19(DQd11-)
ECEn: JP8.2(Pin2) U4.B3(\\~{ECE})
EE_ADDR0_RX: J28.C34 U8.1(A0)
EE_ADDR1_RX: J28.D35 U8.2(A1)
FB+: C3.1 R2.2 U1.4(FB+)
FB-: C13.1 R11.2 U1.7(FB-)
FBQ+: C18.1 R17.2 U2.4(FB+)
FBQ-: C23.1 R24.2 U2.7(FB-)
FMC_ADC_SCSb: J28.H38 ; also on sheet 9
FMC_ADC_SDI: J28.G36 ; also on sheet 9
FMC_DATA: J28.G37 ; also on sheet 9
FMC_LMX_CAL: J28.J15 ; also on sheet 9
FMC_LMX_SCSb: J28.G33 ; also on sheet 9
FMC_LMX_SDI: J28.G19 ; also on sheet 9
FMC_SCL: J28.C30 J30.2 U8.6(SCL)
FMC_SCLK: J28.H37 ; also on sheet 9
FMC_SDA: J28.C31 J30.1 U8.5(SDA)
FSR: JP6.2(Pin2) U4.Y3(FSR)
IN+: C13.2 R6.1 R7.2 R11.1 U1.6(IN+)
IN-: C3.2 R2.1 R3.2 R6.2 U1.5(IN-)
INI_+: J1.1(CENTER) R1.1
INI_-: J3.1(CENTER) R12.1
INQ_+: J4.1(CENTER) R16.1
INQ_-: J6.1(CENTER) R27.1
IPD: JP1.2 R13.1 U1.9(PD)
LMX_CAL: U7.5(CAL) ; also on sheet 9
LMX_CLKM: C41.1 C140.2
LMX_CLKP: C42.1 C136.2
LMX_CSB: TP8.1(TP) U7.39(CSB) ; also on sheet 9
LMX_OSCN: C135.1 U7.13(OSCinM)
LMX_OSCP: C128.1 U7.12(OSCinP)
LMX_SCK: TP6.1(TP) U7.26(SCK) ; also on sheet 9
LMX_SDI: TP7.1(TP) U7.27(SDI) ; also on sheet 9
LMX_SDO: R105.2 ; also on sheet 9
LMX_SYNC: PP1.1 R102.1 U7.9(SYNC)
LSPSM: JP3.2(Pin2) U4.V4(LSPSM)
MISO: U20.21(P2.6/TB0.1) ; also on sheet 9
MOSI: U20.20(P2.5/TB0.0) ; also on sheet 9
MUX_OUT: R105.1 R107.1 TP9.1(TP) U7.32(MUXout)
NDM: JP5.2(Pin2) U4.A5(NDM)
ORI+: J28.H34
ORI-: J28.H35
ORQ+: J28.E30
ORQ-: J28.E31
OUT+: R4.1 U1.13(OUT+)
OUT-: R9.1 U1.12(OUT-)
OUTQ+: R19.1 U2.13(OUT+)
OUTQ-: R23.1 U2.12(OUT-)
OVRI+: D2.1(ANODE) R56.2
OVRI-: C32.2 R31.1 R55.2 U3.2(INA-)
OVRQ+: D4.1(ANODE) R57.2
OVRQ-: C33.2 R36.1 R54.2 U3.6(INB-)
PDI: J7.2 R32.1 U4.U3(PDI)
PDQ: J8.2 R33.1 U4.V3(PDQ)
PG_RX1: J28.F1 J29.2 R112.2
PRSNT_M2C_L: J28.H2 R113.1
QN+: C23.2 R22.1 R24.1 R25.2 U2.6(IN+)
QN-: C18.2 R17.1 R18.2 R22.2 U2.5(IN-)
QPD: JP2.2 R28.1 U2.9(PD)
RCLK+: J14.1(CENTER) U4.Y4(RCLK+)
RCLK-: J17.1(CENTER) U4.W5(RCLK-)
RCOUT1+: J15.1(CENTER) U4.Y5(RCOUT1+)
RCOUT1-: J18.1(CENTER) U4.U6(RCOUT1-)
RCOUT2+: J19.1(CENTER) U4.V6(RCOUT2+)
RCOUT2-: J20.1(CENTER) U4.V7(RCOUT2-)
RECAL_EN: R110.2 R111.1 U7.45(RECAL_EN)
SCLK: U20.40(P2.4/TA1.0) ; also on sheet 9
TCK: J36.7 U20.15(PJ.3/TCK)
TCRIT1: R48.2 R49.2 TP4.1(TP) U5.4(\\~{THERM})
TCRIT2: R47.2 TP3.1(TP) U5.7(\\~{ALERT/THERM2})
TDI: J36.3 U20.13(PJ.1/TDI)
TDI_FMC: J28.D30 J31.1
TDIODE+: J11.1 R43.2 U4.E2(Tdiode+)
TDIODE-: J11.2 R45.2 U4.F3(Tdiode-)
TDIODEN: C37.2 R45.1 U5.3(D-)
TDIODEP: C37.1 R43.1 U5.2(D+)
TDO: J36.1 U20.12(PJ.0/TDO)
TDO_FMC: J28.D31 J31.2
TEST: J36.8 U20.22(TEST/SBWTCK)
TMP461_SMBCLK: R39.2 U5.9(SCL) ; also on sheet 9
TMP461_SMBDAT: R41.2 U5.8(SDA) ; also on sheet 9
TMS: J36.5 U20.14(PJ.2/TMS/ACLK)
TPM: JP4.2(Pin2) R46.1 U4.A4(TPM)
TPM_FMC: J28.H19 R46.2
VA19: R85.1 R86.1 R87.1 R88.1 ; also on sheet 10
VADJ_RX: J28.E39 J28.F40 J28.G39 J28.H40 PP2.1 R112.1 R114.1
VBB: U6.5(VBB)
VBG: J12.2 TP2.1(TP) U4.B1(VBG)
VCM: C15.1 R14.2 R15.1 U1.2(CM) U2.2(CM)
VCMO: J10.2 U4.C2(VCMO)
VIO_B_M2C_RX: J28.J39 J28.K40 R114.2
VTUNE: C130.1 R89.2 U7.55(Vtune)
N20251064: C131.2 R95.1
N20251377: C134.1 R89.1 R90.2 TP5.1(TP)
N20258125: D6.1(ANODE) R107.2
N20447902: D5.2(CATHODE) R49.1
N20601243: D3.1(ANODE) U3.7(OUTB)
N20601382: D1.1(ANODE) U3.1(OUTA)
N20601403: D3.2(CATHODE) R37.1
N20601859: D1.2(CATHODE) R34.1
N20602433: C33.1 D4.2(CATHODE) R36.2 U3.5(INB+)
N20603216: C32.1 D2.2(CATHODE) R31.2 U3.3(INA+)
N20606076: J9.1 R35.2
N21168383: C7.2 L3.1 R9.2
N21168467: C4.1 L1.1 R4.2
N21171643: C5.2 C8.1
N21171649: C5.1 L1.2 L2.1
N21171654: C8.2 L3.2 L4.1
N21171729: C2.1 L2.2
N21171732: C14.1 L4.2
N21175089: J7.1 R29.2
N21175349: J8.1 R30.2
N21187119: C126.1 U4.K2(VBIASI)
N21187126: C125.1 U4.J4(VBIASI)
N21187133: C124.1 U4.D7(VBIASI)
N21188308: C116.1 U4.U7(VBIASQ)
N21188315: C115.1 U4.M4(VBIASQ)
N21188322: C114.1 U4.L2(VBIASQ)
N21202974: R51.1 U4.W3(RSV)
N21203641: C39.2 U4.E3(RSV1)
N21203646: C38.2 U4.F4(RSV2)
N21203848: R42.2 U4.C3(Rext+)
N21203855: R42.1 U4.D3(Rext-)
N21203893: R44.2 U4.C1(Rtrim+)
N21203895: R44.1 U4.D2(Rtrim-)
N21228014: R56.1 U4.K17(ORI+)
N21228016: R55.1 U4.K18(ORI-)
N21228048: R57.1 U4.L17(ORQ+)
N21228050: R54.1 U4.L18(ORQ-)
N21241287: C6.1 R8.1 R10.1
N21267772: C21.2 L7.1 R23.2
N21267797: C19.1 L5.1 R19.2
N21267893: C20.2 C22.1
N21267903: C20.1 L5.2 L6.1
N21267907: C22.2 L7.2 L8.1
N21267936: C17.1 L6.2
N21267939: C24.1 L8.2
N21310593: C153.2 U7.42(VbiasVCO2)
N21313753: C128.2 J22.1(CENTER) R91.1 R93.2 R184.2
N21313758: C135.2 R93.1 R96.1 R185.1
N21321417: C137.1 L9.1 R97.2 R99.1
N21321463: C136.1 R97.1 U7.37(RFoutAP)
N21321475: C140.1 R99.2 U7.36(RFoutAM)
N21324767: R92.2 R184.1 Y1.5(COUTF)
N21324772: R94.2 R185.2 Y1.4(OUTF)
N21375599: C142.1 L10.1 R100.2 R104.1
N21375615: C138.1 R100.1 U7.30(RFoutBP)
N21375619: C144.1 R104.2 U7.29(RFoutBM)
N21375683: C138.2 J26.1(CENTER)
N21375685: C144.2 J27.1(CENTER)
N21382849: C154.2 U7.53(VbiasVRAC)
N21382882: C152.2 U7.44(VrefVCO2)
N21382945: C150.1 U7.56(VrefVCO)
N21382968: C148.2 U7.59(VregVCO)
N21391760: C147.2 U7.14(VregIN)
N21391777: C151.2 U7.7(VbiasVCO)
N21397866: C139.1 R98.2 U7.34(VccBUF)
N21398145: C141.1 R101.2 U7.11(VccDIG)
N21398455: C143.1 R103.2 U7.21(VccCP)
N21398481: C145.1 R106.2 U7.25(VccMASH)
N21398674: C146.1 R108.2 U7.57(VccVCO)
N21398700: C149.1 R109.2 U7.41(VccVCO2)
N21445987: J28.C39 J28.D36 J28.D38 J28.D40 R115.1
N21446161: J28.D1 J29.1
N21451420: C53.1 R61.1 U6.26(Q3)
N21451422: C54.1 R62.1 U6.25(~{Q3})
N21451444: C57.1 R67.1 U6.24(Q4)
N21451446: C58.1 R68.1 U6.23(~{Q4})
N21451502: C62.1 R78.1 U6.19(~{Q6})
N21451579: JP10.2(Pin2) U6.2(CLK_SEL)
N21451692: R79.2 R82.1 U6.6(CLK1)
N21451698: R79.1 R83.1 U6.7(~{CLK1})
N21538078: C16.1 R20.1 R21.1
N21540492: R70.2 R73.1 U6.3(CLK0)
N21540508: R70.1 R75.1 U6.4(~{CLK0})
N21563907: C61.1 R77.1 U6.20(Q6)
N21564155: C60.1 R72.1 U6.21(~{Q5})
N21564157: C59.1 R71.1 U6.22(Q5)
N21602890: J24.1 Y1.1(OE)
N21637810: D10.1(ANODE) R188.2
N21637823: R188.1 U20.1(P1.0/TA0.1/DMAE0)
N21637881: SW1.2 U20.2(P1.1/TA0.2)
N21638540: J35.1 U20.9(P1.3/TA1.2)
N21638545: J35.2 R189.1 TP17.1(TP) U21.2(VN) U22.2(VN)
N21638708: JP13.1(Pin1) U20.11(P1.5/TB0.2)
N21638717: JP12.1(Pin1) U20.10(P1.4/TB0.1)
N21648189: JP12.2(Pin2) TP18.1(TP) U21.1(VP)
N21648194: JP13.2(Pin2) TP19.1(TP) U22.1(VP)
N21648707: C233.1 R187.2 U20.48(AVCC)
N21648712: C231.2 C232.2 C233.2 R186.2 U20.44(AVSS) U20.47(AVSS)
N21649143: C231.1 U20.46(PJ.5/LFXOUT) Y3.1
N21649147: C232.1 U20.45(PJ.4/LFXIN) Y3.2
N21650021: C235.1 U20.42(PJ.6/XFZIN) Y4.2
N21650025: C234.1 U20.43(PJ.7/ZFXOUT) Y4.1
N21650057: C234.2 C235.2 U20.41(AVSS)

Not connected (* = marked no-connect by the designer): J28 A2 A3 A6 A7 A10 A11 A14 A15 A18 A19 A22 A23 A26 A27 A30 A31 A34 A35 A38 A39 B1 B4 B5 B8 B9 B12 B13 B16 B17 B20 B21 B24 B25 B28 B29 B32 B33 B36 B37 B40 C2 C3 C6 C7 C18 C19 C20 D4 D5 D17 D18 D19 D29 D33 D34 E8 E12 E13 E14 E15 E16 E18 E19 E33 E34 E36 E37 F6 F16 F17 F19 F20 F34 F35 F37 F38 G2 G3 G17 G34 H1 H4 H5 H6 H15 H18 H20 J2 J3 J4 J16 J17 J18 J19 J21 J22 J23 J33 J34 J36 J37 K1 K2 K4 K5 K12 K16 K17 K19 K20 K22 K23 K34 K35 K37 K38; J36 2 6 10 12 13 14; T1 2(NOTUSED)*; U6 11(~{Q9}) 12(Q9) 13(~{Q8}) 14(Q8) 15(~{Q7}) 16(Q7) 29(~{Q2}) 30(Q2) 31(~{Q1}) 32(Q1) 33(~{Q0}) 34(Q0); U7 1(NC1)* 2(NC2)* 33(NC3)* 46(NC4)* 47(NC5)* 48(NC6)* 49(NC7)* 50(NC8)* 52(NC9)* 58(NC10)* 62(NC11)* 63(NC12)* 64(NC13)*; U20 3(P1.2/TA1.1) 4(P3.0/A12/C12) 5(P3.1/A13/C13) 6(P3.2/A14/C14) 7(P3.3/A15/C15) 8(P4.7) 16(P4.0/A8) 17(P4.1/A9) 18(P4.2/A10) 19(P4.3/A11) 24(P2.0/TB0.6) 25(P2.1/TB0.0) 26(P2.2/TB0.2) 27(P3.4/TB0.3/SMCLK) 28(P3.5/TB0.4/COUT) 29(P3.6/TB0.5) 30(P3.7/TB0.6) 31(P1.6/TB0.3) 32(P1.7/TB0.4) 33(P4.4/TB0.5) 34(P4.5) 35(P4.6) 38(P2.7); Y1 2(NC2)*

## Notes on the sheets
sheet 2
- MSP430
- PAGES 8
- POWER
- SUPPLIES
- USB
- LEVEL SHIFTERS
- PAGES 10, 11
- PAGES 9
- SPI
- ANALOG INPUT
    CHANNEL A
- LVDS DATA
- PAGE 2
- ADC12D1620-SP
- SYNCB
- FMC
- CONNECTOR
- PAGES 3, 4, 5
- SPI
- PAGES 7
- ANALOG INPUT
    CHANNEL B
- PAGE 2
- EXT CLK
- LMXCLK
- LMX2615
- PAGE 6
- 12500 TI Boulevard. Dallas, Texas 75243
- Engineer:
- J BRINKHURST  06/2018
- PCB:
- JV SMITH  05/2018
sheet 3
- SHARED PAD
- SHARED PAD
- SHARED PAD
- SHARED PAD
- 12500 TI Boulevard. Dallas, Texas 75243
sheet 4
- 12500 TI Boulevard. Dallas, Texas 75243
sheet 7
- 12500 TI Boulevard. Dallas, Texas 75243
